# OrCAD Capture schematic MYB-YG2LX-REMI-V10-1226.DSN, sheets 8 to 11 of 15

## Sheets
8 DSI - HDMI & LVDS: size A2; note: Dispaly
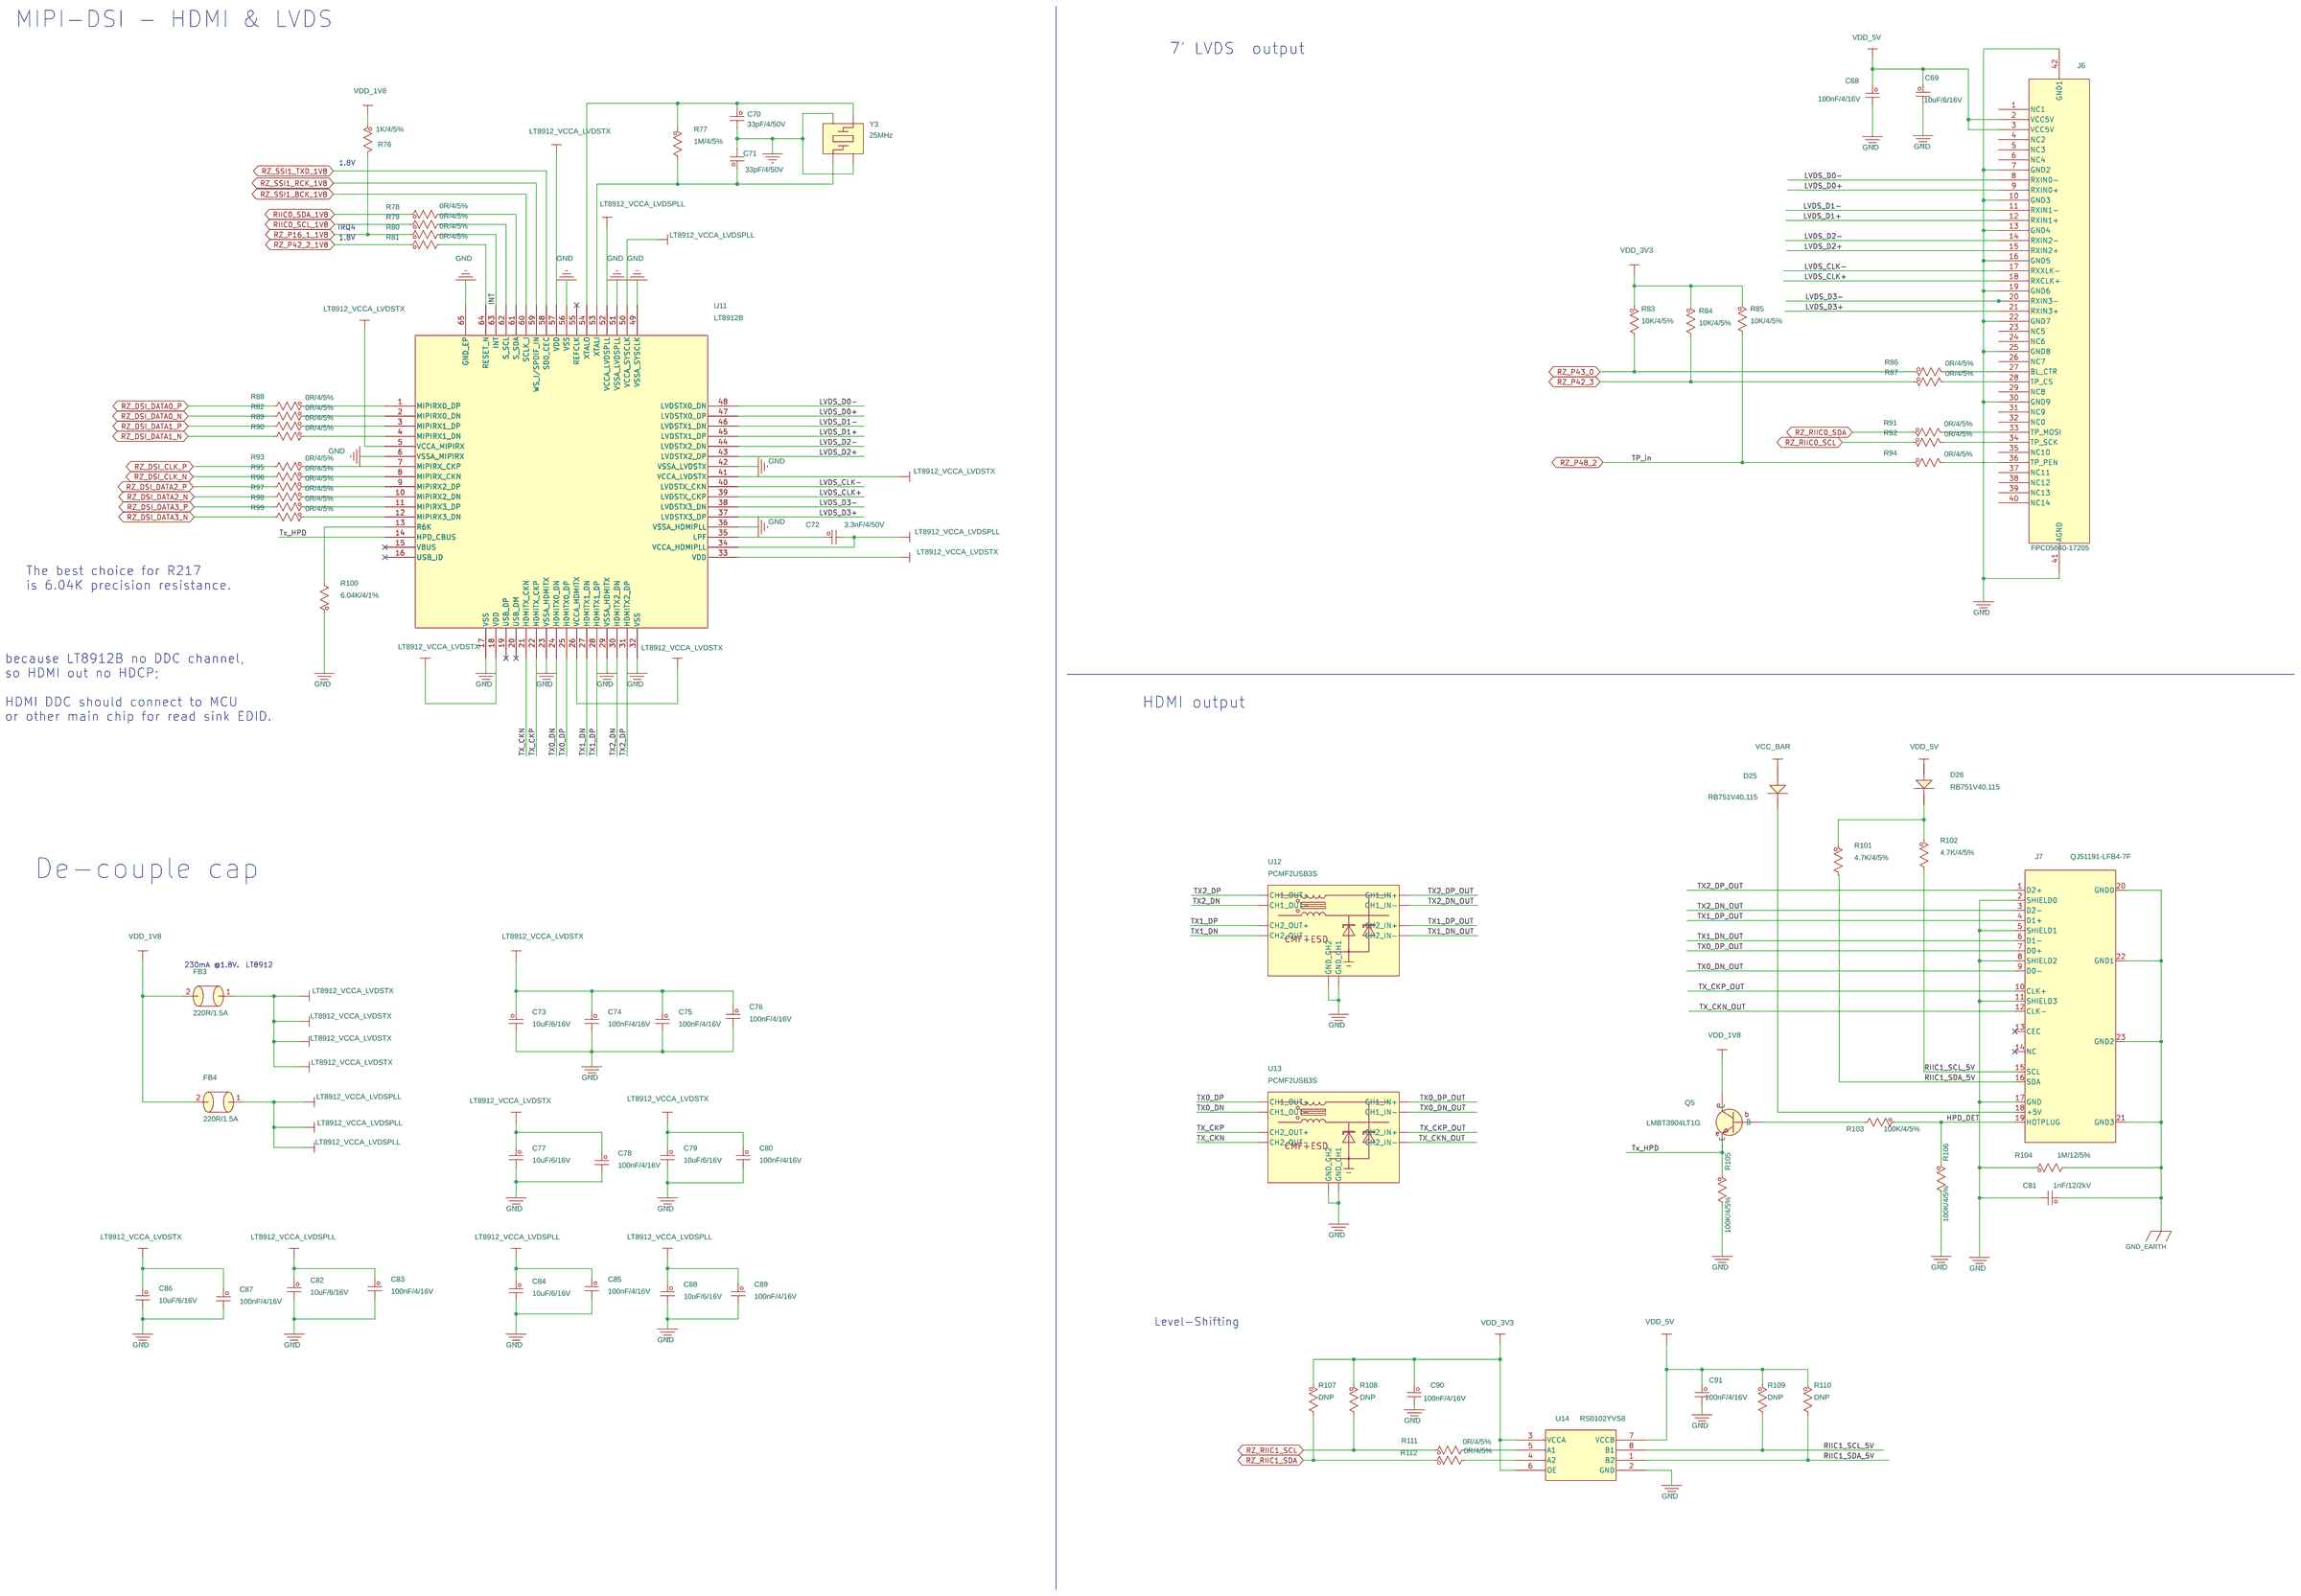
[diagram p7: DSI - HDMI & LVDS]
9 Audio: size A3; note: Audio
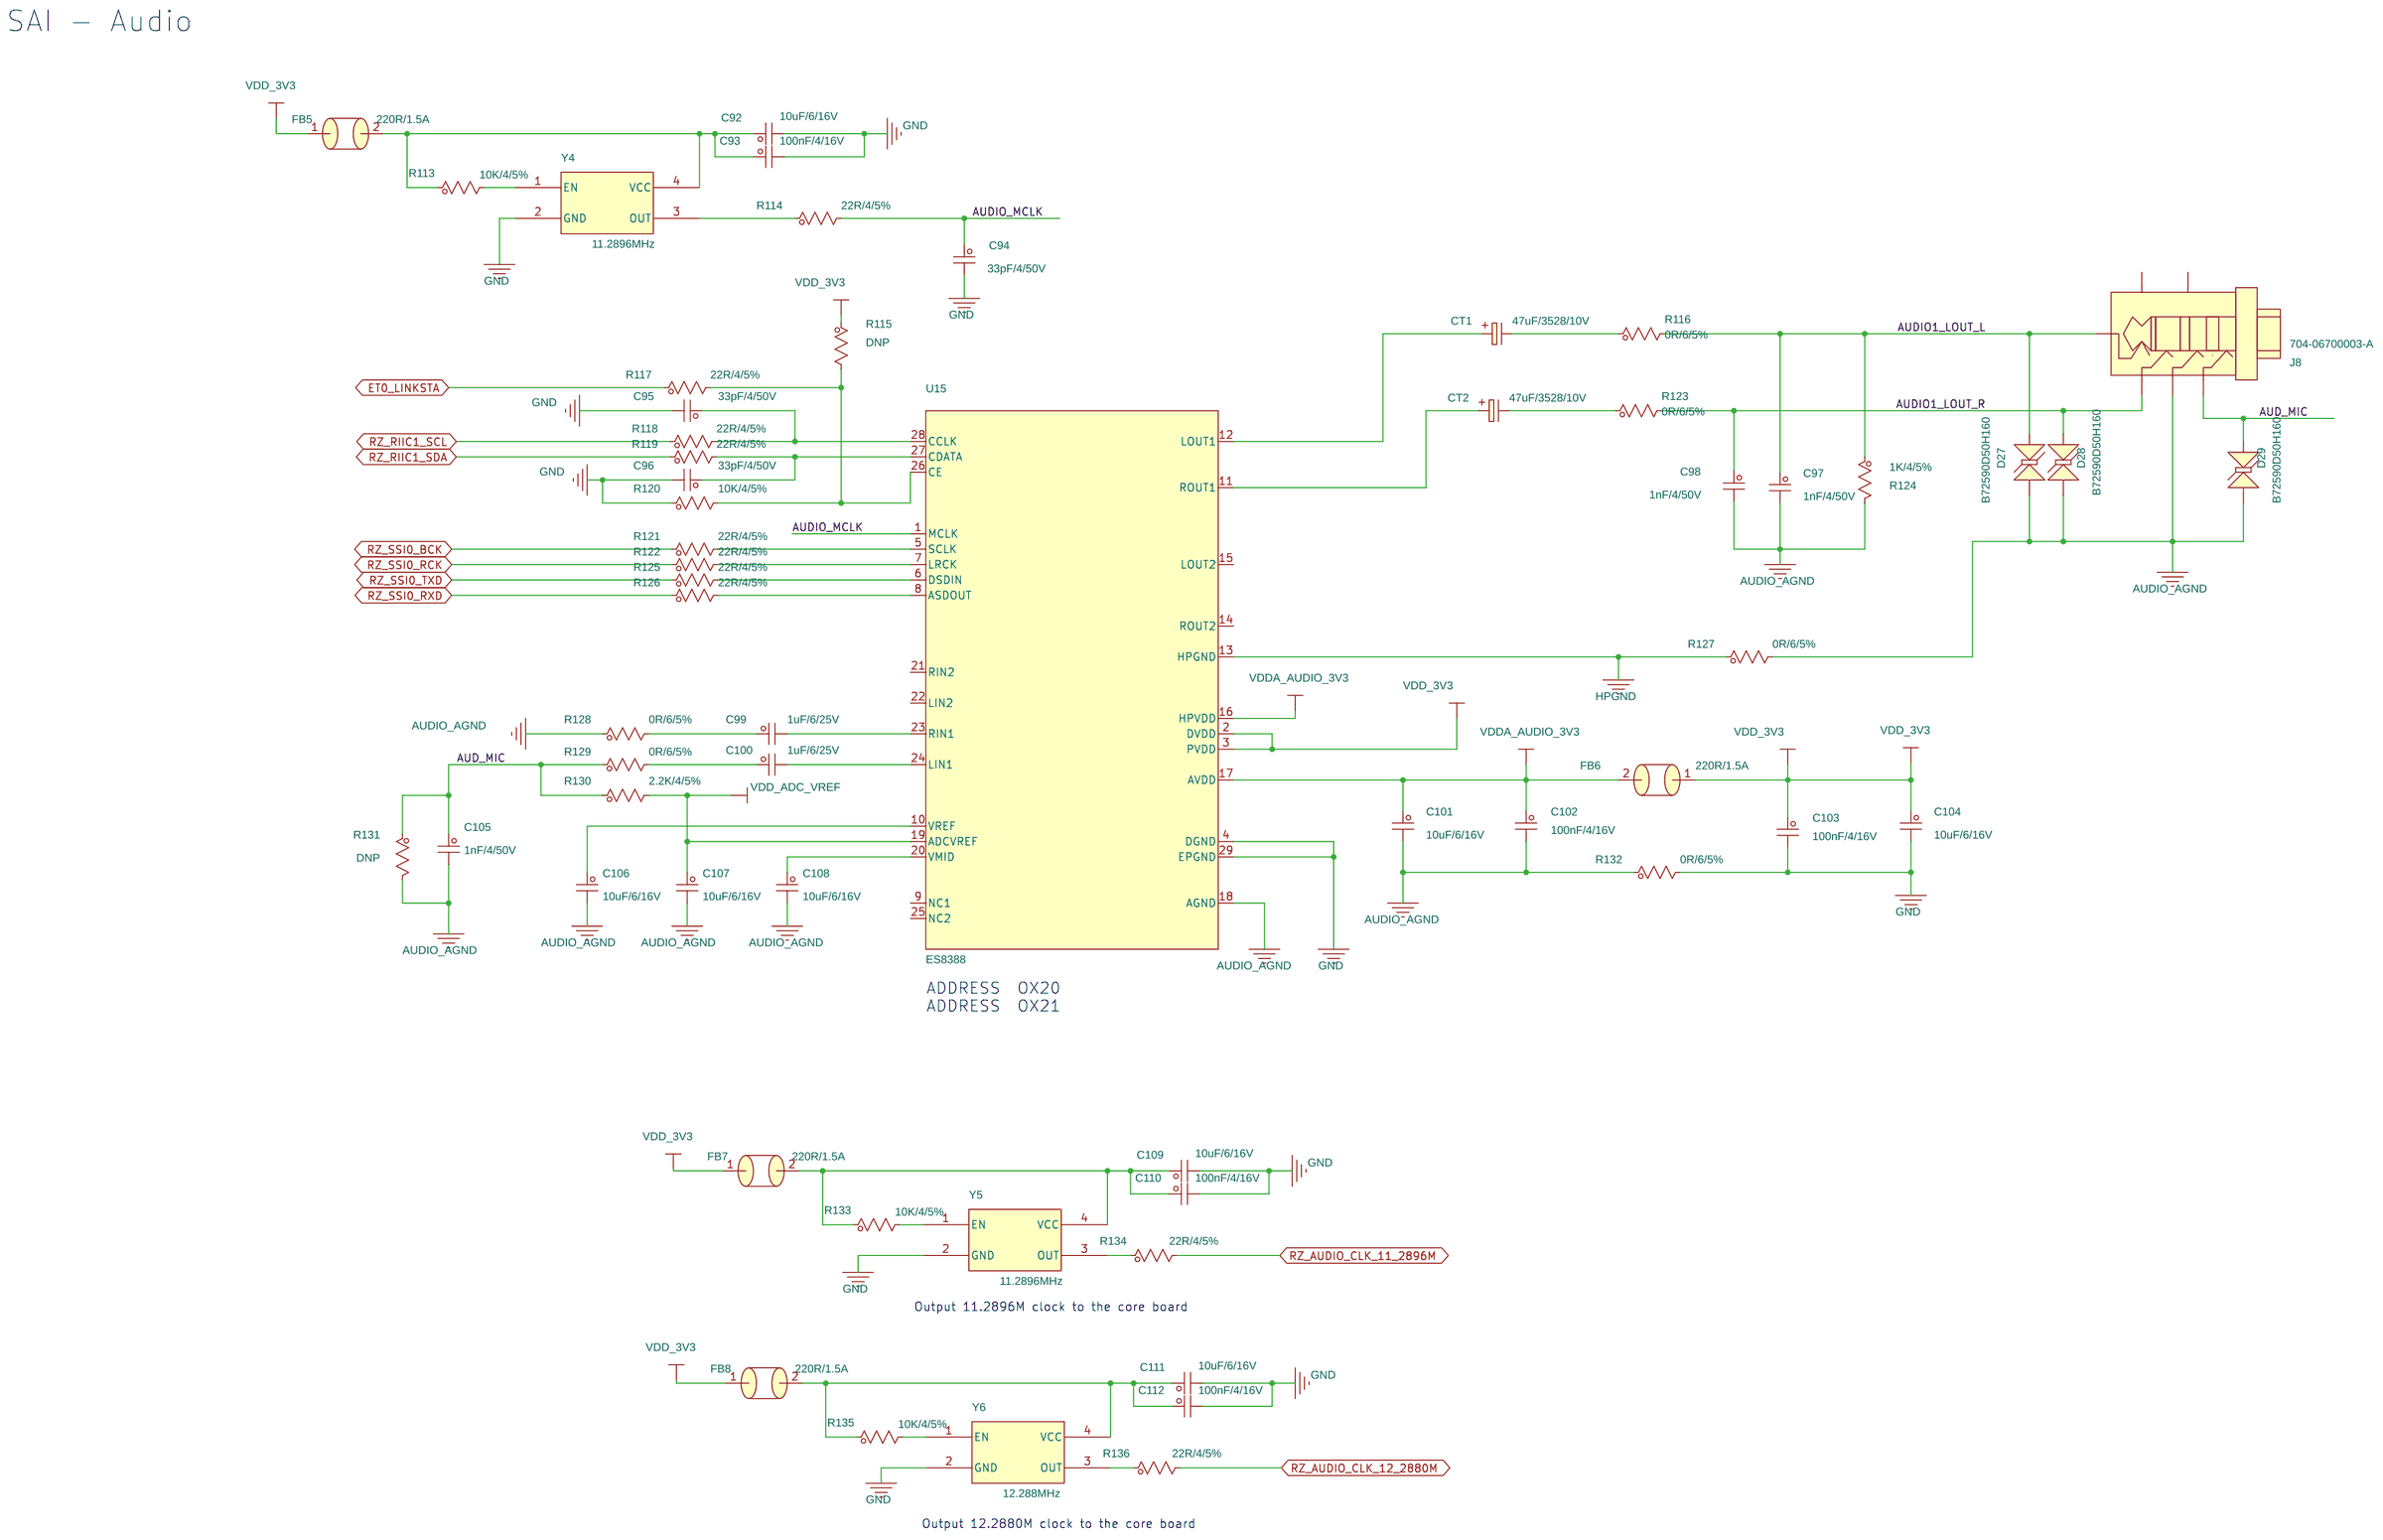
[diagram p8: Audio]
10 ENET0 & ENET1: size A2; note: ENET
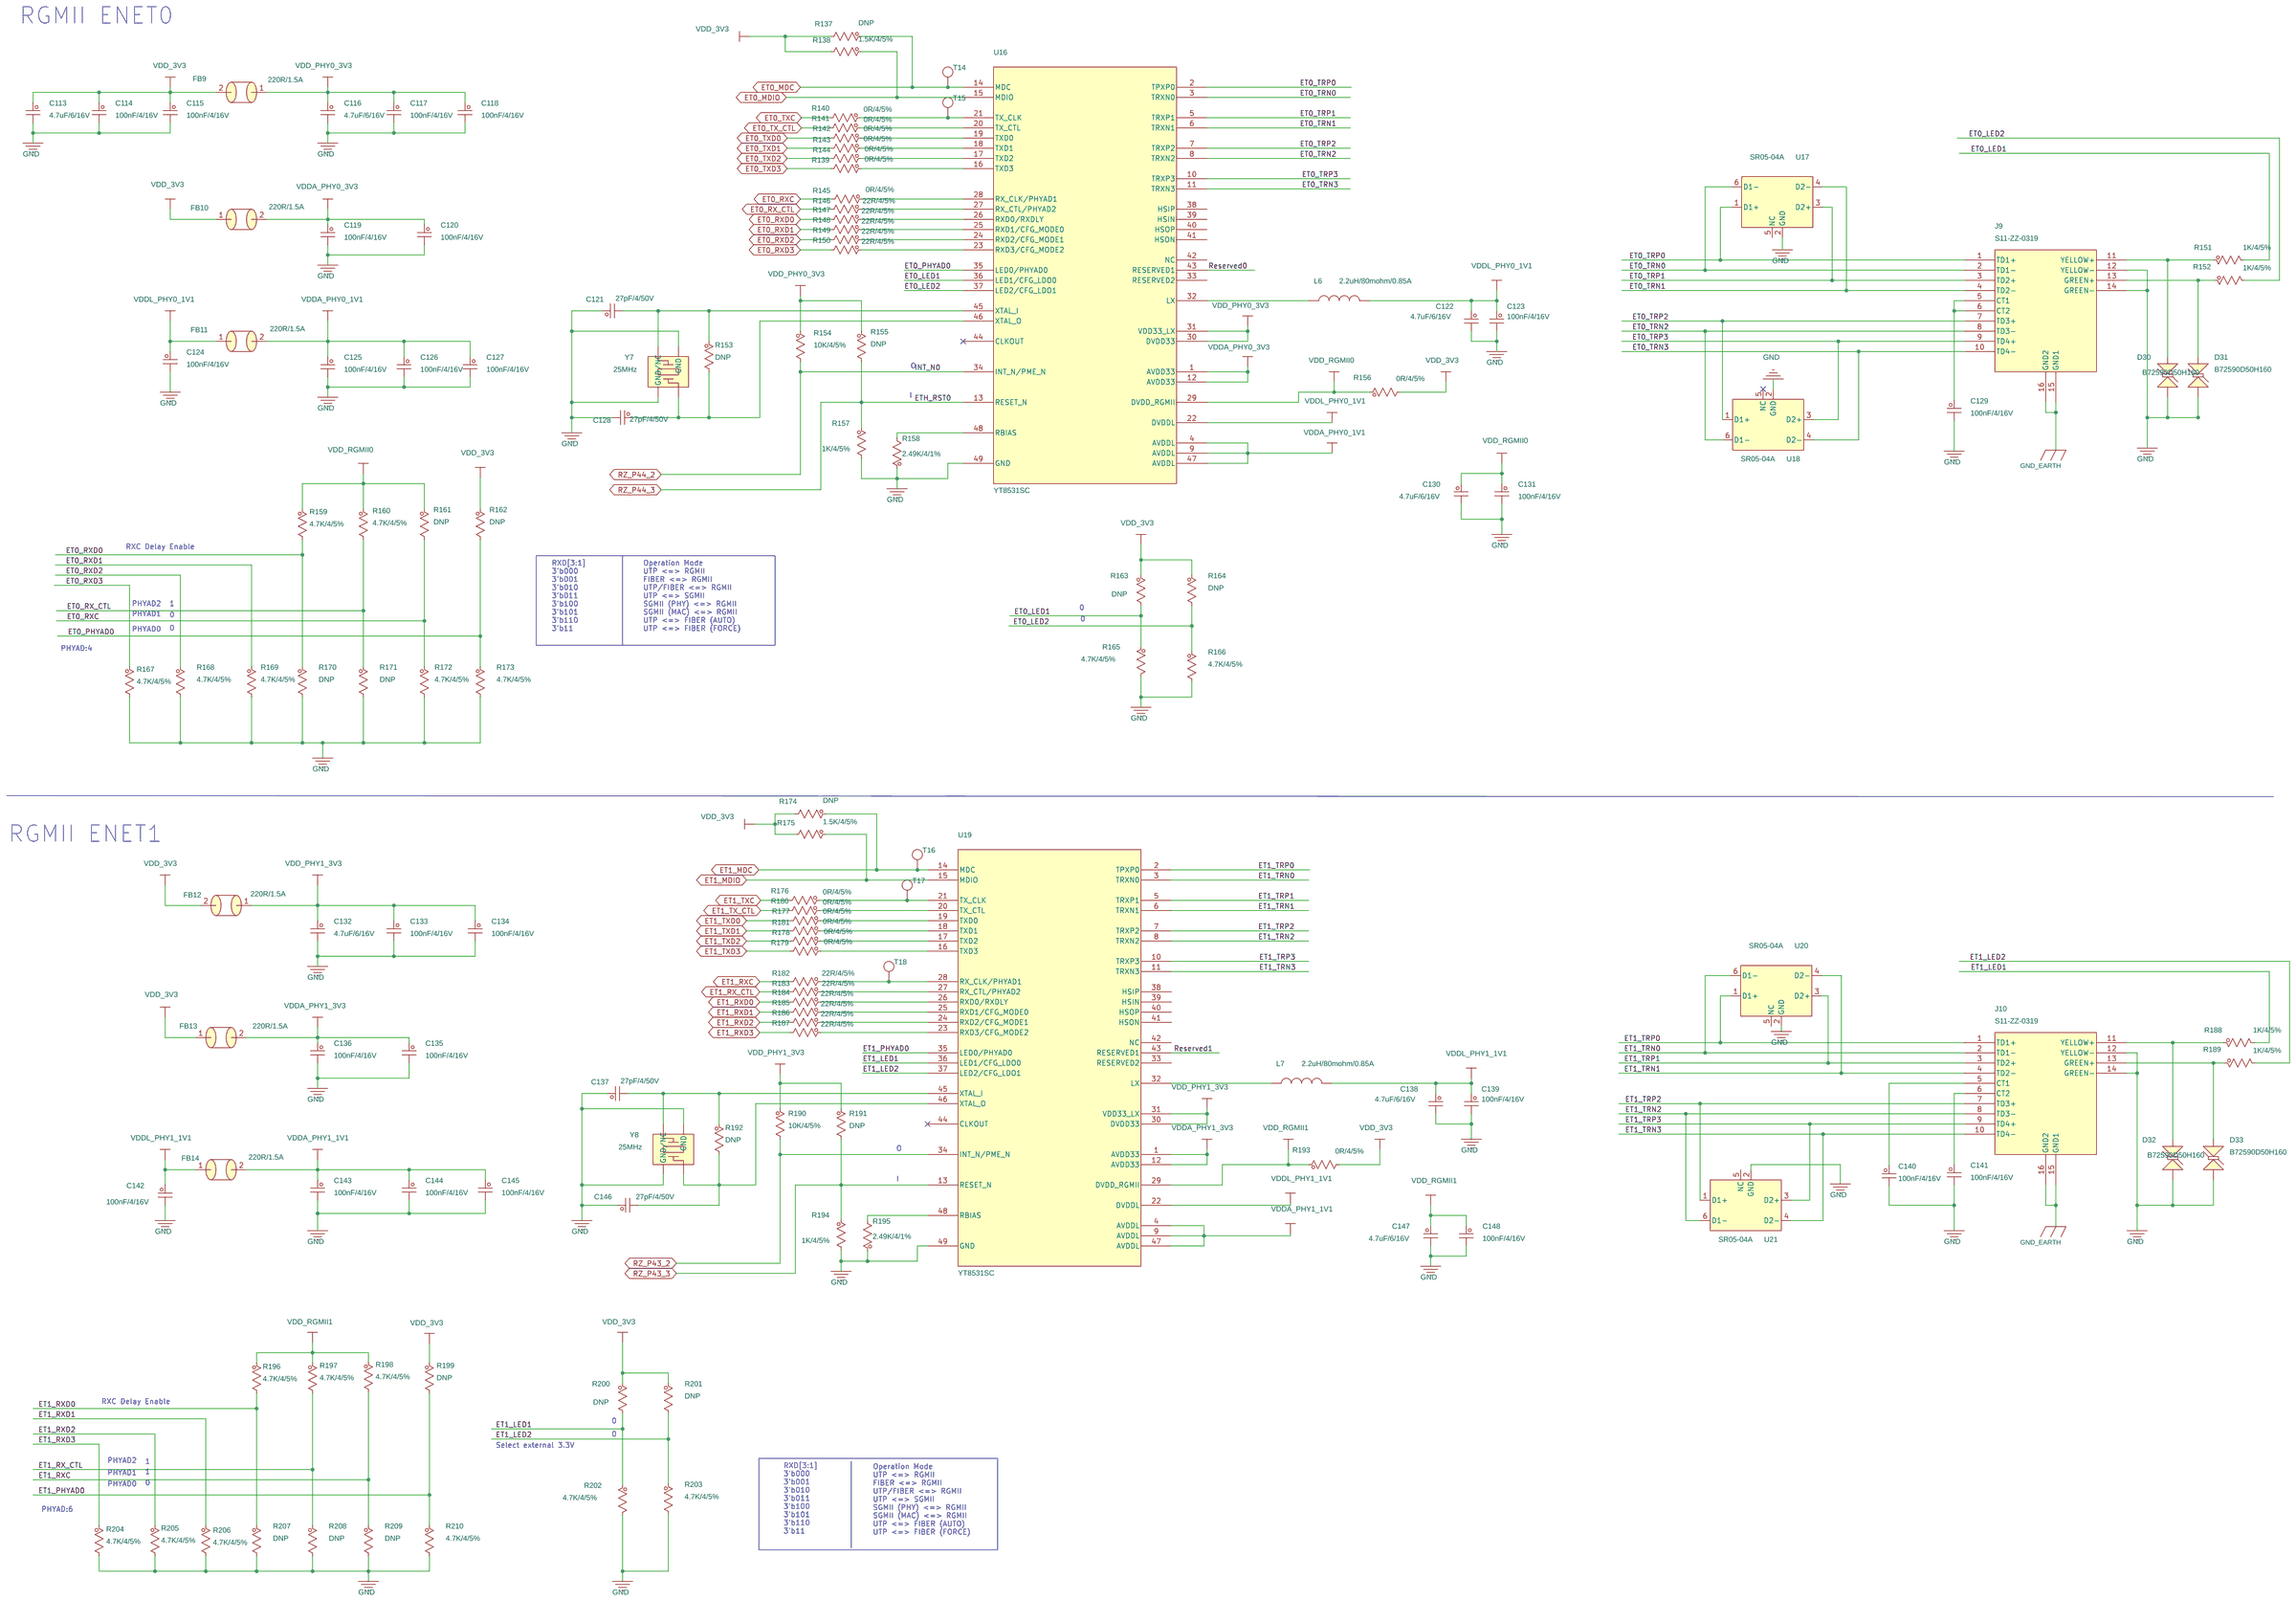
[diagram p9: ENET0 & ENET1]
11 WIFI & BT: size A2; note: MISC
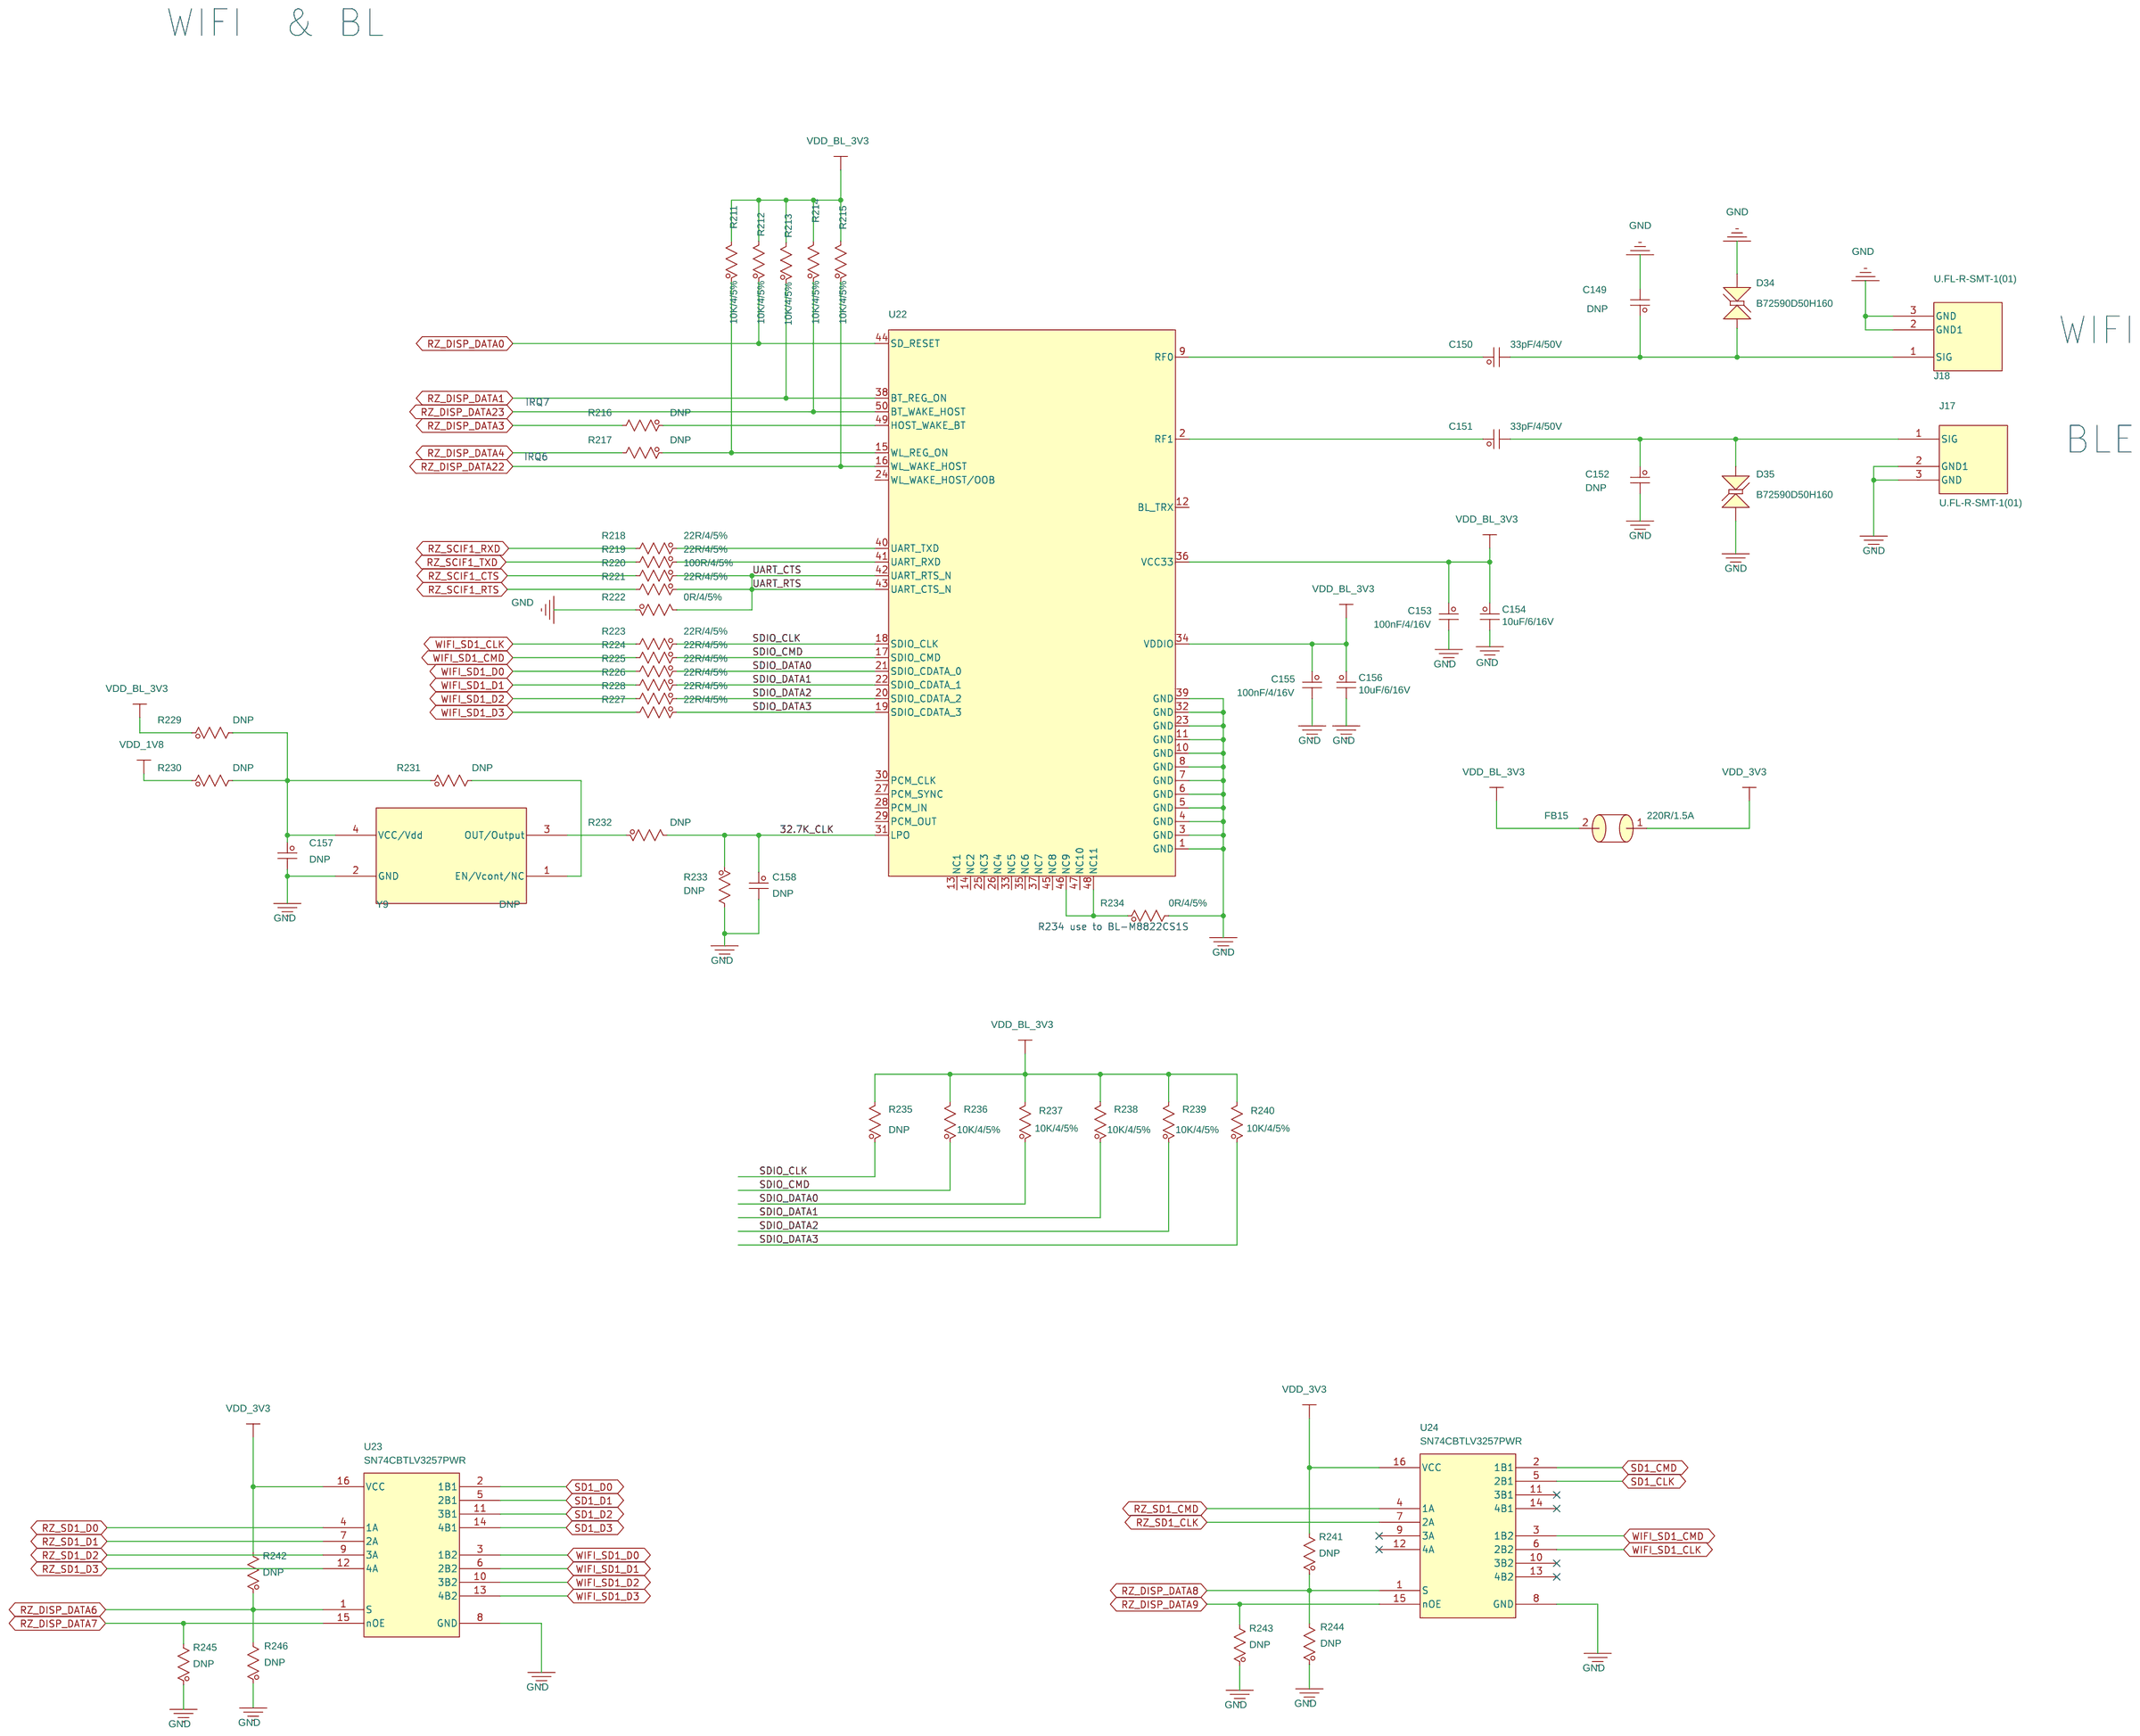
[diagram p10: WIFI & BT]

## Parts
sheet Audio
C92  10uF/6/16V  [C0603]
C93  100nF/4/16V  [C0402]
C94  33pF/4/50V  [C0402]
C95  33pF/4/50V  [C0402]
C96  33pF/4/50V  [C0402]
C97  1nF/4/50V  [C0402]
C98  1nF/4/50V  [C0402]
C99  1uF/6/25V  [C0603]
C100  1uF/6/25V  [C0603]
C101  10uF/6/16V  [C0603]
C102  100nF/4/16V  [C0402]
C103  100nF/4/16V  [C0402]
C104  10uF/6/16V  [C0603]
C105  1nF/4/50V  [C0402]
C106  10uF/6/16V  [C0603]
C107  10uF/6/16V  [C0603]
C108  10uF/6/16V  [C0603]
C109  10uF/6/16V  [C0603]
C110  100nF/4/16V  [C0402]
C111  10uF/6/16V  [C0603]
C112  100nF/4/16V  [C0402]
CT1  47uF/3528/10V  [CT3528-B]
CT2  47uF/3528/10V  [CT3528-B]
D27  B72590D50H160  [D0402]
D28  B72590D50H160  [D0402]
D29  B72590D50H160  [D0402]
FB5  220R/1.5A  [FB0603]
FB6  220R/1.5A  [FB0603]
FB7  220R/1.5A  [FB0603]
FB8  220R/1.5A  [FB0603]
J8  704-06700003-A  [CKX-704]
R113  10K/4/5%  [R0402]
R114  22R/4/5%  [R0402]
R115  DNP  [R0402]
R116  0R/6/5%  [R0603]
R117  22R/4/5%  [R0402]
R118  22R/4/5%  [R0402]
R119  22R/4/5%  [R0402]
R120  10K/4/5%  [R0402]
R121  22R/4/5%  [R0402]
R122  22R/4/5%  [R0402]
R123  0R/6/5%  [R0603]
R124  1K/4/5%  [R0402]
R125  22R/4/5%  [R0402]
R126  22R/4/5%  [R0402]
R127  0R/6/5%  [R0603]
R128  0R/6/5%  [R0603]
R129  0R/6/5%  [R0603]
R130  2.2K/4/5%  [R0402]
R131  DNP  [R0402]
R132  0R/6/5%  [R0603]
R133  10K/4/5%  [R0402]
R134  22R/4/5%  [R0402]
R135  10K/4/5%  [R0402]
R136  22R/4/5%  [R0402]
U15  ES8388  [QFN28-0_45]
Y4  11.2896MHz  [3225]
Y5  11.2896MHz  [3225]
Y6  12.288MHz  [3225]
sheet DSI - HDMI & LVDS
C68  100nF/4/16V  [C0402]
C69  10uF/6/16V  [C0603]
C70  33pF/4/50V  [C0402]
C71  33pF/4/50V  [C0402]
C72  3.3nF/4/50V  [C0402]
C73  10uF/6/16V  [C0603]
C74  100nF/4/16V  [C0402]
C75  100nF/4/16V  [C0402]
C76  100nF/4/16V  [C0402]
C77  10uF/6/16V  [C0603]
C78  100nF/4/16V  [C0402]
C79  10uF/6/16V  [C0603]
C80  100nF/4/16V  [C0402]
C81  1nF/12/2kV  [C1206]
C82  10uF/6/16V  [C0603]
C83  100nF/4/16V  [C0402]
C84  10uF/6/16V  [C0603]
C85  100nF/4/16V  [C0402]
C86  10uF/6/16V  [C0603]
C87  100nF/4/16V  [C0402]
C88  10uF/6/16V  [C0603]
C89  100nF/4/16V  [C0402]
C90  100nF/4/16V  [C0402]
C91  100nF/4/16V  [C0402]
D25  RB751V40,115  [SOD323]
D26  RB751V40,115  [SOD323]
FB3  220R/1.5A  [FB0603]
FB4  220R/1.5A  [FB0603]
J6  FPC05040-17205  [FPC40-0_5-h]
J7  QJ51191-LFB4-7F  [QJ51191-LFB4]
Q5  LMBT3904LT1G  [SOT-23]
R76  1K/4/5%  [R0402]
R77  1M/4/5%  [R0402]
R78  0R/4/5%  [R0402]
R79  0R/4/5%  [R0402]
R80  0R/4/5%  [R0402]
R81  0R/4/5%  [R0402]
R82  0R/4/5%  [R0402]
R83  10K/4/5%  [R0402]
R84  10K/4/5%  [R0402]
R85  10K/4/5%  [R0402]
R86  0R/4/5%  [R0402]
R87  0R/4/5%  [R0402]
R88  0R/4/5%  [R0402]
R89  0R/4/5%  [R0402]
R90  0R/4/5%  [R0402]
R91  0R/4/5%  [R0402]
R92  0R/4/5%  [R0402]
R93  0R/4/5%  [R0402]
R94  0R/4/5%  [R0402]
R95  0R/4/5%  [R0402]
R96  0R/4/5%  [R0402]
R97  0R/4/5%  [R0402]
R98  0R/4/5%  [R0402]
R99  0R/4/5%  [R0402]
R100  6.04K/4/1%  [R0402]
R101  4.7K/4/5%  [R0402]
R102  4.7K/4/5%  [R0402]
R103  100K/4/5%  [R0402]
R104  1M/12/5%  [R1206]
R105  100K/4/5%  [R0402]
R106  100K/4/5%  [R0402]
R107  DNP  [R0402]
R108  DNP  [R0402]
R109  DNP  [R0402]
R110  DNP  [R0402]
R111  0R/4/5%  [R0402]
R112  0R/4/5%  [R0402]
U11  LT8912B  [qfn64-0_4-LT8912B]
U12  PCMF2USB3S  [WLCSP10]
U13  PCMF2USB3S  [WLCSP10]
U14  RS0102YVS8  [VSSOP8]
Y3  25MHz  [3225]
sheet ENET0 & ENET1
C113  4.7uF/6/16V  [C0603]
C114  100nF/4/16V  [C0402]
C115  100nF/4/16V  [C0402]
C116  4.7uF/6/16V  [C0603]
C117  100nF/4/16V  [C0402]
C118  100nF/4/16V  [C0402]
C119  100nF/4/16V  [C0402]
C120  100nF/4/16V  [C0402]
C121  27pF/4/50V  [C0402]
C122  4.7uF/6/16V  [C0603]
C123  100nF/4/16V  [C0402]
C124  100nF/4/16V  [C0402]
C125  100nF/4/16V  [C0402]
C126  100nF/4/16V  [C0402]
C127  100nF/4/16V  [C0402]
C128  27pF/4/50V  [C0402]
C129  100nF/4/16V  [C0402]
C130  4.7uF/6/16V  [C0603]
C131  100nF/4/16V  [C0402]
C132  4.7uF/6/16V  [C0603]
C133  100nF/4/16V  [C0402]
C134  100nF/4/16V  [C0402]
C135  100nF/4/16V  [C0402]
C136  100nF/4/16V  [C0402]
C137  27pF/4/50V  [C0402]
C138  4.7uF/6/16V  [C0603]
C139  100nF/4/16V  [C0402]
C140  100nF/4/16V  [C0402]
C141  100nF/4/16V  [C0402]
C142  100nF/4/16V  [C0402]
C143  100nF/4/16V  [C0402]
C144  100nF/4/16V  [C0402]
C145  100nF/4/16V  [C0402]
C146  27pF/4/50V  [C0402]
C147  4.7uF/6/16V  [C0603]
C148  100nF/4/16V  [C0402]
D30  B72590D50H160  [D0402]
D31  B72590D50H160  [D0402]
D32  B72590D50H160  [D0402]
D33  B72590D50H160  [D0402]
FB9  220R/1.5A  [FB0603]
FB10  220R/1.5A  [FB0603]
FB11  220R/1.5A  [FB0603]
FB12  220R/1.5A  [FB0603]
FB13  220R/1.5A  [FB0603]
FB14  220R/1.5A  [FB0603]
J9  S11-ZZ-0319  [S11-ZZ-0319]
J10  S11-ZZ-0319  [S11-ZZ-0319]
L6  2.2uH/80mohm/0.85A  [L2x2_5]
L7  2.2uH/80mohm/0.85A  [L2x2_5]
R137  DNP  [R0402]
R138  1.5K/4/5%  [R0402]
R139  0R/4/5%  [R0402]
R140  0R/4/5%  [R0402]
R141  0R/4/5%  [R0402]
R142  0R/4/5%  [R0402]
R143  0R/4/5%  [R0402]
R144  0R/4/5%  [R0402]
R145  0R/4/5%  [R0402]
R146  22R/4/5%  [R0402]
R147  22R/4/5%  [R0402]
R148  22R/4/5%  [R0402]
R149  22R/4/5%  [R0402]
R150  22R/4/5%  [R0402]
R151  1K/4/5%  [R0402]
R152  1K/4/5%  [R0402]
R153  DNP  [R0402]
R154  10K/4/5%  [R0402]
R155  DNP  [R0402]
R156  0R/4/5%  [R0402]
R157  1K/4/5%  [R0402]
R158  2.49K/4/1%  [R0402]
R159  4.7K/4/5%  [R0402]
R160  4.7K/4/5%  [R0402]
R161  DNP  [R0402]
R162  DNP  [R0402]
R163  DNP  [R0402]
R164  DNP  [R0402]
R165  4.7K/4/5%  [R0402]
R166  4.7K/4/5%  [R0402]
R167  4.7K/4/5%  [R0402]
R168  4.7K/4/5%  [R0402]
R169  4.7K/4/5%  [R0402]
R170  DNP  [R0402]
R171  DNP  [R0402]
R172  4.7K/4/5%  [R0402]
R173  4.7K/4/5%  [R0402]
R174  DNP  [R0402]
R175  1.5K/4/5%  [R0402]
R176  0R/4/5%  [R0402]
R177  0R/4/5%  [R0402]
R178  0R/4/5%  [R0402]
R179  0R/4/5%  [R0402]
R180  0R/4/5%  [R0402]
R181  0R/4/5%  [R0402]
R182  22R/4/5%  [R0402]
R183  22R/4/5%  [R0402]
R184  22R/4/5%  [R0402]
R185  22R/4/5%  [R0402]
R186  22R/4/5%  [R0402]
R187  22R/4/5%  [R0402]
R188  1K/4/5%  [R0402]
R189  1K/4/5%  [R0402]
R190  10K/4/5%  [R0402]
R191  DNP  [R0402]
R192  DNP  [R0402]
R193  0R/4/5%  [R0402]
R194  1K/4/5%  [R0402]
R195  2.49K/4/1%  [R0402]
R196  4.7K/4/5%  [R0402]
R197  4.7K/4/5%  [R0402]
R198  4.7K/4/5%  [R0402]
R199  DNP  [R0402]
R200  DNP  [R0402]
R201  DNP  [R0402]
R202  4.7K/4/5%  [R0402]
R203  4.7K/4/5%  [R0402]
R204  4.7K/4/5%  [R0402]
R205  4.7K/4/5%  [R0402]
R206  4.7K/4/5%  [R0402]
R207  DNP  [R0402]
R208  DNP  [R0402]
R209  DNP  [R0402]
R210  4.7K/4/5%  [R0402]
T14  SMD  [test0_8-smd]
T15  SMD  [test0_8-smd]
T16  SMD  [test0_8-smd]
T17  SMD  [test0_8-smd]
T18  SMD  [test0_8-smd]
U16  YT8531SC  [QFN48-0_4]
U17  SR05-04A  [SOT23-6]
U18  SR05-04A  [SOT23-6]
U19  YT8531SC  [QFN48-0_4]
U20  SR05-04A  [SOT23-6]
U21  SR05-04A  [SOT23-6]
Y7  25MHz  [3225]
Y8  25MHz  [3225]
sheet WIFI & BT
C149  DNP  [C0402]
C150  33pF/4/50V  [C0402]
C151  33pF/4/50V  [C0402]
C152  DNP  [C0402]
C153  100nF/4/16V  [C0402]
C154  10uF/6/16V  [C0603]
C155  100nF/4/16V  [C0402]
C156  10uF/6/16V  [C0603]
C157  DNP  [C0402]
C158  DNP  [C0402]
D34  B72590D50H160  [D0402]
D35  B72590D50H160  [D0402]
FB15  220R/1.5A  [FB0603]
J17  U.FL-R-SMT-1(01)  [FL_2d95x1d55_2sp]
J18  U.FL-R-SMT-1(01)  [FL_2d95x1d55_2sp]
R211  10K/4/5%  [R0402]
R212  10K/4/5%  [R0402]
R213  10K/4/5%  [R0402]
R214  10K/4/5%  [R0402]
R215  10K/4/5%  [R0402]
R216  DNP  [R0402]
R217  DNP  [R0402]
R218  22R/4/5%  [R0402]
R219  22R/4/5%  [R0402]
R220  100R/4/5%  [R0402]
R221  22R/4/5%  [R0402]
R222  0R/4/5%  [R0402]
R223  22R/4/5%  [R0402]
R224  22R/4/5%  [R0402]
R225  22R/4/5%  [R0402]
R226  22R/4/5%  [R0402]
R227  22R/4/5%  [R0402]
R228  22R/4/5%  [R0402]
R229  DNP  [R0402]
R230  DNP  [R0402]
R231  DNP  [R0402]
R232  DNP  [R0402]
R233  DNP  [R0402]
R234  0R/4/5%  [R0402]
R235  DNP  [R0402]
R236  10K/4/5%  [R0402]
R237  10K/4/5%  [R0402]
R238  10K/4/5%  [R0402]
R239  10K/4/5%  [R0402]
R240  10K/4/5%  [R0402]
R241  DNP  [R0402]
R242  DNP  [R0402]
R243  DNP  [R0402]
R244  DNP  [R0402]
R245  DNP  [R0402]
R246  DNP  [R0402]
U22  BL-M8822CS1S  [MODULE-L297B-SR]
U23  SN74CBTLV3257PWR  [TSSOP16]
U24  SN74CBTLV3257PWR  [TSSOP16]
Y9  DNP  [3225]

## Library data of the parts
C92 C109 C111 = CERAMIC_CAPACITOR: Ceramic Capacitor,10uF,16V,+/-20%,X5R,0603,Samsung; Manufacturer: Samsung; Manufacturer P/N: CL10A106MONQNC; Myir P/N: 20401.80062; Part Type: Ceramic Capacitor; Reserve Value: 10uF; Datasheet: Samsung.pdf
C68 C74-C76 C78 C80 C83 C85 C87 C89-C91 C93 C102 C103 C110 C112 C114 C115 C117-C120 C123-C127 C129 C131 C133-C136 C139-C145 C148 C153 C155 C157 C158 = Ceramic_Capacitor: Ceramic Capacitor,100nF,16V,+/-10%,X7R,0402,Fenghua; Manufacturer: Fenghua; Manufacturer P/N: 0402B104K160NT; Myir P/N: 20401.80188; Part Type: Ceramic Capacitor; Reserve Value: 100nF; Datasheet: FENGHUA-Capacitor.pdf
C70 C71 C94-C96 C150 C151 = Ceramic_Capacitor: Ceramic Capacitor,33pF,50V,+/-5%,C0G,0402,Fenghua; Manufacturer: Fenghua; Manufacturer P/N: 0402CG330J500NT; Myir P/N: 20401.00091; Part Type: Ceramic Capacitor; Reserve Value: 33pF; Datasheet: FENGHUA-Capacitor.pdf
C97 C98 C105 = Ceramic_Capacitor: Ceramic Capacitor,1nF,50V,+/-10%,X7R,0402,Fenghua; Manufacturer: Fenghua; Manufacturer P/N: 0402B102K500NT; Myir P/N: 20401.80096; Part Type: Ceramic Capacitor; Reserve Value: 1nF; Datasheet: FENGHUA-Capacitor.pdf
C99 C100 = Ceramic_Capacitor: Ceramic Capacitor,1uF,+/-10%,X5R,SMT,25V,0603,Samsung; Manufacturer: Samsung; Manufacturer P/N: CL10A105KA8NNNC; Myir P/N: 20401.80063; Part Type: Ceramic Capacitor; Reserve Value: 1uF; Datasheet: Samsung.pdf
C101 C104 C106-C108 C154 C156 = Ceramic_Capacitor: Ceramic Capacitor,10uF,+/-20%,X5R,16V,SMD,0603,Samsung; Manufacturer: Samsung; Manufacturer P/N: CL10A106MO8NQNC; Myir P/N: 20401.80062; Part Type: Ceramic Capacitor; Reserve Value: 10uF; Datasheet: Samsung.pdf
CT1 CT2 = Tantalum_Capacitor: Tantalum Capacitor,47uF,+/-10%,10V,SMD,3528(B),AVX; Manufacturer: AVX; Manufacturer P/N: TAJB476K010RNJ; Myir P/N: 20403.00006; Part Type: Tantalum Capacitor; Reserve Value: 47uF; Datasheet: Tantalum Capacitor.pdf
D27-D35 = TVS_Diode: Diode,TVS,5.6VDC,SMD,D0402,TDK; Manufacturer: TDK; Myir P/N: 20701.00001; Part Type: Diode; Datasheet: B72590D0050H160.pdf
FB3-FB15 = Ferrite_Bead: Ferrite Bead,220R@100Mhz,1.5A,+/-25%,SMD,0603,Fenghua; Manufacturer: Fenghua; Manufacturer P/N: CBM160808U221T; Myir P/N: 20601.80007; Part Type: Ferrite Bead; Reserve Value: 220R; Datasheet: CBM160808U221T.pdf
J8 = Audio-704-06700003-A: Connector,Φ3.50mm with 4 Pole with single audio jack,SMD,Reel,SongCheng; Manufacturer: SongCheng; Myir P/N: 21116.00006; Part Type: Audio Connector; Datasheet: 704-06700003-A.pdf
R83-R85 R113 R133 R135 R163 R164 R200 R201 = Resister: Thick Film Resistor,10K,+/-5%,1/16W,-55°C ~ 155°C,SMD,0402,Fenghua; Manufacturer: Fenghua; Manufacturer P/N: RC-02W103JT; Myir P/N: 20301.00199; Part Type: Thick Film Resistor; Reserve Value: 10K; Datasheet: FH规格书_2018-07-30.pdf
R114 R216-R219 R221 R223-R228 = Resister: Thick Film Resistor,22R,+/-5%,1/16W,-55℃~155℃,SMD,0402,Fenghua; Manufacturer: Fenghua; Manufacturer P/N: RC-02W220JT; Myir P/N: 20301.00187; Part Type: Thick Film Resistor; Reserve Value: 22R; Datasheet: FHsheet_2018-07-30.PDF
R115 R154 R155 R190 R191 = Resister: Thick Film Resistor,10K,+/-5%,1/16W,-55°C ~ 155°C,SMD,0402,Fenghua; Manufacturer: Fenghua; Manufacturer P/N: RC-02W103JT; Myir P/N: 20301.00199; Part Type: Thick Film Resistor; Reserve Value: 10K; Datasheet: FHsheet_2018-07-30.PDF
R116 R123 R127 R132 = Resister: Thick Film Resistor,0R,+/-5%,1/10W,-55°C ~ 155°C,SMD,0603,Fenghua; Manufacturer: Fenghua; Manufacturer P/N: RS-03000JT; Myir P/N: 20301.00214; Part Type: Thick Film Resistor; Reserve Value: 0R; Datasheet: FHsheet_2018-07-30.PDF
R117-R119 R121 R122 R125 R126 = Resister: Thick Film Resistor,22R,+/-5%,1/16W,-55℃~155℃,SMD,0402,Fenghua; Manufacturer: Fenghua; Manufacturer P/N: RC-02K220JT; Myir P/N: 20301.00187; Part Type: Thick Film Resistor; Reserve Value: 22R; Datasheet: FHsheet-20230524.pdf
R120 = Resister: Thick Film Resistor,10K,+/-5%,1/16W,-55℃~155℃,SMD,0402,Fenghua; Manufacturer: Fenghua; Manufacturer P/N: RC-02K103JT; Myir P/N: 20301.00199; Part Type: Thick Film Resistor; Reserve Value: 10K; Datasheet: FHsheet-20230524.pdf
R124 = Resister: Thick Film Resistor,1K,+/-5%,1/16W,-55℃~155℃,SMD,0402,Fenghua; Manufacturer: Fenghua; Manufacturer P/N: RC-02K102JT; Myir P/N: 20301.80389; Part Type: Thick Film Resistor; Reserve Value: 1K; Datasheet: FHsheet-20230524.pdf
R128 R129 = Resister: Thick Film Resistor,0R,+/-5%,1/10W,-55℃~155℃,SMD,0603,Fenghua; Manufacturer: Fenghua; Manufacturer P/N: RS-03000JT; Myir P/N: 20301.00214; Part Type: Thick Film Resistor; Reserve Value: 0R; Datasheet: FHsheet-20230524.pdf
R130 = Resister: Thick Film Resistor,2.2K,+/-5%,1/16W,-55℃~155℃,SMD,0402,Fenghua; Manufacturer: Fenghua; Manufacturer P/N: RC-02K222JT; Myir P/N: 20301.00195; Part Type: Thick Film Resistor; Reserve Value: 2.2K; Datasheet: FHsheet-20230524.pdf
R131 = Resister: Thick Film Resistor,2.2K,+/-5%,1/16W,-55℃~155℃,SMD,0402,Fenghua; Manufacturer: Fenghua; Manufacturer P/N: RC-02W222JT; Myir P/N: 20301.00195; Part Type: Thick Film Resistor; Reserve Value: 2.2K; Datasheet: FHsheet_2018-07-30.PDF
R134 R136 = Resister: Thick Film Resistor,22R,+/-5%,1/16W,-55°C ~ 155°C,SMD,0402,Fenghua; Manufacturer: Fenghua; Manufacturer P/N: RC-02W220JT; Myir P/N: 20301.00187; Part Type: Thick Film Resistor; Reserve Value: 22R; SIGNAL_MODEL: RESISTER_R0402_22/4/5%_22/4/5%; Datasheet: FH规格书_2018-07-30.pdf
U15 = ES8388: IC,Low Power Stereo Audio CODEC With Headphone Amplifier,-40~85℃,SMD,QFN28,Tray,Everest; Manufacturer: Everest; Myir P/N: 20107.00093; Part Type: Interface; Datasheet: ES8388DS.pdf
Y4 Y5 = Oscillator_4P_v3: Oscillator,11.2896MHz,+/-20ppm,15pF,3.3V,4Pin,3225,-40℃ to +85℃,SMD,SJK; Manufacturer: SJK; Manufacturer P/N: SJK-3N11289M3C0420B8; Myir P/N: 20902.00016; Part Type: Oscillator; Datasheet: SJK-3N11289M3C0420B8.pdf
Y6 = Oscillator_4P_v3: Oscillator,12.2880MHz,+/-20ppm,15pF,3.3V,4Pin,3225,-40℃ to +85℃,SMD,SJK; Manufacturer: SJK; Manufacturer P/N: SJK-3N12288M3C0420B8; Myir P/N: 20902.00015; Part Type: Oscillator; Datasheet: SJK-3N12288M3C0420B8.pdf
C69 C73 C77 C79 C82 C84 C86 C88 = Ceramic_Capacitor: Ceramic Capacitor,10uF,16V,+/-20%,X5R,0603,Samsung; Manufacturer: Samsung; Manufacturer P/N: CL10A106MONQNC; Myir P/N: 20401.80062; Part Type: Ceramic Capacitor; Reserve Value: 10uF; Datasheet: Samsung.pdf
C72 = Ceramic_Capacitor: Ceramic Capacitor,3.3nF, 50V,+/-10%,,X7R,0402,Fenghua; Manufacturer: Fenghua; Manufacturer P/N: 0402B332K500NT; Myir P/N: 20401.80104; Part Type: Ceramic Capacitor; Reserve Value: 3.3nF; Datasheet: FENGHUA-Capacitor.pdf
C81 = Ceramic_Capacitor: Ceramic Capacitor,1nF,+/-10%,2kV,X7R,SMD,1206,Fenghua; Manufacturer: Fenghua; Manufacturer P/N: 1206B102K202NT; Myir P/N: 20401.00078; Part Type: Ceramic Capacitor; Reserve Value: 1nF; Datasheet: FENGHUA-Capacitor.pdf
D25 D26 = General_Diode: Diode Schottky, 40V 0.12A,SMD  2-Pin SOD-323,W8,NXP; Manufacturer: NXP; Myir P/N: 20701.00009; Part Type: Diode; Datasheet: RB751_SER.pdf
J6 = FPC40: FPC Connector,40pin,0.5mm pitch,Dual-sided Contact Models, Operating temperature range from–45~85℃,Atom; Manufacturer: Atom; Myir P/N: 21106.00016; Part Type: FPC Connector; Datasheet: FPC_Atom.pdf
J7 = HDMI: Connector,HDMI A port,x1,Right Angle,Female,Gold Flash 1u,black,SMD,Foxconn; Manufacturer: Foxconn; Myir P/N: 21108.00004; Part Type: Display Connector; Datasheet: QJ51191-LFB4-7F.pdf
Q5 = NPN_Transistor: BJT,NPN,40V,200mA,SMD,SOT-23,LRC; Manufacturer: LRC; Myir P/N: 20702.00005; Part Type: BJT; Datasheet: LMBT3904LT1G.pdf
R76 R233 R241-R246 = Resister: Thick Film Resistor,1K,+/-5%,1/16W,-55°C ~ 155°C,SMD,0402,Fenghua; Manufacturer: Fenghua; Manufacturer P/N: RC-02W102JT; Myir P/N: 20301.80389; Part Type: Thick Film Resistor; Reserve Value: 1K; Datasheet: FHsheet_2018-07-30.PDF
R77 = Resister: Thick Film Resistor,1M,+/-5%,1/16W,-55°C ~ 155°C,SMD,0402,Fenghua; Manufacturer: Fenghua; Manufacturer P/N: RC-02W105JT; Myir P/N: 20301.00248; Part Type: Thick Film Resistor; Reserve Value: 1M; Datasheet: FH规格书_2018-07-30.pdf
R78-R82 R86-R99 R111 R112 R139-R145 R156 R176-R181 R193 = Resister: Thick Film Resistor,0R,+/-5%,1/16W,-55°C ~ 155°C,SMD,0402,Fenghua; Manufacturer: Fenghua; Manufacturer P/N: RC-02000JT; Myir P/N: 20301.00186; Part Type: Thick Film Resistor; Reserve Value: 0R; Datasheet: FH规格书_2018-07-30.pdf
R100 = Resister: Thick Film Resistor,6.04K,+/-1%,1/16W,-55°C ~ 155°C,SMD,0402,Fenghua; Manufacturer: Fenghua; Manufacturer P/N: RC-02W6041FT; Myir P/N: 20301.00270; Part Type: Thick Film Resistor; Reserve Value: 6.04K; Datasheet: FH规格书_2018-07-30.pdf
R101 R102 R159-R162 R165-R173 R196-R199 R202-R210 = Resister: Thick Film Resistor,4.7K,+/-5%,1/16W,-55°C ~ 155°C,SMD,0402,Fenghua; Manufacturer: Fenghua; Manufacturer P/N: RC-02W472JT; Myir P/N: 20301.80393; Part Type: Thick Film Resistor; Reserve Value: 4.7K; Datasheet: FH规格书_2018-07-30.pdf
R103 R105 R106 = Resister: Thick Film Resistor,100K,+/-5%,,1/16W,-55°C ~ 155°C,SMD,0402,Fenghua; Manufacturer: Fenghua; Manufacturer P/N: RC-02W104JT; Myir P/N: 20301.00210; Part Type: Thick Film Resistor; Reserve Value: 100K; Datasheet: FH规格书_2018-07-30.pdf
R104 = Resister: Thick Film Resistor,1M,+/-5%,1/4W,-55°C ~ 155°C,SMD,1206,Fenghua; Manufacturer: Fenghua; Manufacturer P/N: RS-06K105JT; Myir P/N: 20301.00226; Part Type: Thick Film Resistor; Reserve Value: 1M; Datasheet: FH规格书_2018-07-30.pdf
R107-R110 = RESISTER: Thick Film Resistor,2.2K,+/-5%,1/16W,-55°C ~ 155°C,SMD,0402,Fenghua; Manufacturer: Fenghua; Manufacturer P/N: RC-02W222JT; Myir P/N: 20301.00195; Part Type: Thick Film Resistor; Reserve Value: 2.2K; Datasheet: FH规格书_2018-07-30.pdf
U11 = LT8912B: IC,LT8912 Single-Channel MIPI? DSI Bridge to LVDS/HDMI,Single 1.8V supply power, ?40°C to +85°C,QFN64(7.5*7.5),Lontium Semiconductor.; Manufacturer: Lontium Semiconductor; Myir P/N: 20107.00050; Part Type: Interface; Datasheet: LT8912_Datasheet_R1.11.pdf
U12 U13 = PCMF2USB3S: IC,Common-mode EMI filter for 2 channels with integrated ESD protection,SMD,WLCSP10,PF2S,NXP; Manufacturer: NXP; Myir P/N: 20114.00011; Part Type: Protection; Datasheet: PCMFxUSB3S.pdf
U14 = TXS0102DCT: IC,2-Bit Bidirectional Voltage-Level Translator for Open-Drain and Push-Pull Application,SMD,VSSOP8,Runic; Manufacturer: Runic; Myir P/N: 20105.00030; Part Type: Logic; Datasheet: RS0102.pdf
Y3 = Crystal_4P: Crystal,25MHz,+/-10ppm,18pF,4Pin,3225,-40℃to+85℃,SMD,SJK; Manufacturer: SJK; Manufacturer P/N: SJK-7U25000MAH1430B8; Myir P/N: 20901.00029; Part Type: Crystal; RP1 Manufacturer P/N: 7V25000025; RP1 Myir P/N: 20901.00005; RP2 Manufacturer P/N: E3FB25E000012E; RP2 Myir P/N: 20901.00020; Datasheet: 7U25000MAH1430B8.pdf
C113 C116 C122 C130 C132 C138 C147 = Ceramic_Capacitor: Ceramic Capacitor,4.7uF,16V, +/-10%,X5R,0603,Samsung; Manufacturer: Samsung; Manufacturer P/N: CL10A475KO8NNNC; Myir P/N: 20401.80066; Part Type: Ceramic Capacitor; Reserve Value: 4.7uF; Datasheet: Samsung.pdf
C121 C128 C137 C146 = Ceramic_Capacitor: Ceramic Capacitor,27pF,50V,+/-5%,C0G,0402,Fenghua; Manufacturer: Fenghua; Manufacturer P/N: 0402CG270J500NT; Myir P/N: 20401.00097; Part Type: Ceramic Capacitor; Reserve Value: 27pF; Datasheet: FENGHUA-Capacitor.pdf
J9 J10 = S11-ZZ-0319: Connector,RJ45 1X1,10/100/1000 Base-T,LED:L-Green; R-Yellow,Gold Flash,-40 °C~+85°C,UDE; Manufacturer: UDE; Myir P/N: 21118.00010; Part Type: ETH Connector; Datasheet: RJ45-UDE_S11-ZZ-0319(20130-00)-A.pdf
L6 L7 = Inductor: Power Inductor,2.2uH 20%,80mOhm 0.85A ,SMD 2.5*2.0*1.0mm,Sunlord; Manufacturer: Sunlord; Manufacturer P/N: MPH252010S2R2MT; Myir P/N: 20501.00042; Part Type: Power Inductor; Reserve Value: 2.2uH; Datasheet: MPH252010S2R2M.pdf
R137 R138 R153 R174 R175 R192 = Resister: Thick Film Resistor,1.5K,+/-5%,1/16W,-55°C ~ 155°C,SMD,0402,Fenghua; Manufacturer: Fenghua; Manufacturer P/N: RC-02W152JT; Myir P/N: 20301.00194; Part Type: Thick Film Resistor; Reserve Value: 1.5K; Datasheet: FH规格书_2018-07-30.pdf
R146-R150 R182-R187 = Resister: Thick Film Resistor,22R,+/-5%,1/16W,-55°C ~ 155°C,SMD,0402,Fenghua; Manufacturer: Fenghua; Manufacturer P/N: RC-02W220JT; Myir P/N: 20301.00187; Part Type: Thick Film Resistor; Reserve Value: 22R; Datasheet: FH规格书_2018-07-30.pdf
R151 R152 R188 R189 = Resister: Thick Film Resistor,1K,+/-5%,1/16W,-55°C ~ 155°C,SMD,0402,Fenghua; Manufacturer: Fenghua; Manufacturer P/N: RC-02W102JT; Myir P/N: 20301.80389; Part Type: Thick Film Resistor; Reserve Value: 1K; Datasheet: FH规格书_2018-07-30.pdf
R157 R194 = Resister: Thick Film Resistor,1K,+/-5%,1/16W,-55℃~155℃,SMD,0402,Fenghua; Manufacturer: Fenghua; Manufacturer P/N: RC-02W102JT; Myir P/N: 20301.80389; Part Type: Thick Film Resistor; Reserve Value: 1K; Datasheet: FHsheet_2018-07-30.PDF
R158 R195 = Resister: Thick Film Resistor,2.49K,+/- 1%,1/16W,-55°C ~ 155°C,SMD,0402,Fenghua; Manufacturer: Fenghua; Manufacturer P/N: RC-02W2491FT; Myir P/N: 20301.00249; Part Type: Thick Film Resistor; Reserve Value: 2.49K; Datasheet: FH规格书_2018-07-30.pdf
T14-T18 = TP: DESIG: testing PAD; FAB: NA; REF: NA; VAL: NOT POPULATED
U16 U19 = YT8521SH: IC,Ethernet Physical Layer Transceiver,Consumer,10/100/1000M,0~C~+70~C,Commercial,SMD,QFN48,Motorcomm; Manufacturer: Motorcomm; Myir P/N: 20107.00088; Part Type: Interface; Datasheet: YT8531SH_YT8531SC_Datasheet_draft.pdf
U17 U18 U20 U21 = TPD4E1U06: IC,Quad-Channel,High-Speed ESD Protection Device,SMD,SOT23-6,UN; Manufacturer: UN; Myir P/N: 20114.00013; Part Type: Protection; RP1 Manufacturer P/N: TPD4E1U06DBVR; RP1 Myir P/N: 20114.00004; Datasheet: SR05-04A.pdf
Y7 Y8 = Crystal_0: Crystal,25MHz,+/-10ppm,18pF,4Pin,3225,-40℃to+85℃,SMD,SJK; Manufacturer: SJK; Manufacturer P/N: SJK-7U25000MAH1430B8; Myir P/N: 20901.00029; Part Type: Crystal; RP1 Manufacturer P/N: 7V25000025; RP1 Myir P/N: 20901.00005; RP2 Manufacturer P/N: E3FB25E000012E; RP2 Myir P/N: 20901.00020; Datasheet: 7U25000MAH1430B8.pdf
C149 C152 = Ceramic_Capacitor: Ceramic Capacitor,10nF,50V,+/-10%,X7R,0402,Fenghua; Manufacturer: Fenghua; Manufacturer P/N: 0402B103K500NT; Myir P/N: 20401.80103; Part Type: Ceramic Capacitor; Reserve Value: 10nF; Datasheet: FENGHUA-Capacitor.pdf
J17 J18 = U_1.FL-LP-040: RF Connector,1 Contact(s),Male, Board Mount,Surface Mount Terminal,UMCC RCP 0Hz to 6GHz 50Ohm Solder ST SMD Gold Over Nickel,HRS; Manufacturer: HRS; Myir P/N: 21114.80006; Part Type: Antenna Connector; Datasheet: UFL Series.pdf
R211-R215 R236-R240 = RESISTER: Thick Film Resistor,10K,+/-5%,1/16W,-55℃~155℃,SMD,0402,Fenghua; Manufacturer: Fenghua; Manufacturer P/N: RC-02K103JT; Myir P/N: 20301.00199; Part Type: Thick Film Resistor; Reserve Value: 10K; Datasheet: FHsheet-20230524.pdf
R220 = Resister: Thick Film Resistor,100R,+/-5%,1/16W,-55℃~155℃,SMD,0402,Fenghua; Manufacturer: Fenghua; Manufacturer P/N: RC-02K101JT; Myir P/N: 20301.00191; Part Type: Thick Film Resistor; Reserve Value: 100R; Datasheet: FHsheet-20230524.pdf
R222 R234 = RESISTER: Thick Film Resistor,0R,+/-5%,1/16W,-55℃~155℃,SMD,0402,Fenghua; Manufacturer: Fenghua; Manufacturer P/N: RC-02000JT; Myir P/N: 20301.00186; Part Type: Thick Film Resistor; Reserve Value: 0R; Datasheet: FHsheet-20230524.pdf
R229-R231 = Resister: Thick Film Resistor,4.7K,+/-5%,1/16W,-55°C ~ 155°C,SMD,0402,Fenghua; Manufacturer: Fenghua; Manufacturer P/N: RC-02W472JT; Myir P/N: 20301.80393; Part Type: Thick Film Resistor; Reserve Value: 4.7K; Datasheet: FHsheet_2018-07-30.PDF
R232 = Resister: Thick Film Resistor,0R,+/-5%,1/16W,-55°C ~ 155°C,SMD,0402,Fenghua; Manufacturer: Fenghua; Manufacturer P/N: RC-02000JT; Myir P/N: 20301.00186; Part Type: Thick Film Resistor; Reserve Value: 0R; Datasheet: FHsheet_2018-07-30.PDF
R235 = RESISTER: Thick Film Resistor,10K,+/-5%,1/16W,-55°C ~ 155°C,SMD,0402,Fenghua; Manufacturer: Fenghua; Manufacturer P/N: RC-02W103JT; Myir P/N: 20301.00199; Part Type: Thick Film Resistor; Reserve Value: 10K; Datasheet: FHsheet_2018-07-30.PDF
U22 = FG6222BSRC-E0: WIFI/Bluetooth Module,802.11a/b/g/n/ac 2T2R WiFi + Bluetooth 4.2 SDIO Module,-10~70℃,Size 15.1*13.1*2.4mm,SMD,REEL,LB-LINK; Manufacturer: LB-LINK; Myir P/N: 20201.00012; Part Type: WIFI Module; Datasheet: BL-M8822CS1-2.pdf
U23 U24 = SN74CBTLV3257: IC,Low-Voltage 4-Bit 1-of-2 FET Multiplexer,SMD,TSSOP16,CL257,TI; Manufacturer: TI; Myir P/N: 20105.00006; Part Type: Logic; Datasheet: sn74cbtlv3257.pdf
Y9 = Oscillator_4P: Oscillator,32.768KHz,+/-30ppm,15pF,3.3V,4Pin,3225,-40℃to+85℃,SMD,SJK; Manufacturer: SJK; Manufacturer P/N: SJK-3N32768K3C0430B8; Myir P/N: 20902.00010; Part Type: Oscillator; RP1 Manufacturer P/N: HSO321S-32.768KHz; RP1 Myir P/N: 20902.00002; Reserve Value: 32.768kHZ; Datasheet: 3N32768K3C0430B8.pdf

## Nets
GND: C68.2 C69.2 C70.2 C71.2 C73.2 C74.2 C75.2 C76.2 C77.2 C78.2 C79.2 C80.2 C81.2 C82.2 C83.2 C84.2 C85.2 C86.2 C87.2 C88.2 C89.2 C90.2 C91.2 C92.2 C93.2 C94.2 C95.2 C96.2 C103.2 C104.2 C109.2 C110.2 C111.2 C112.2 C113.2 C114.2 C115.2 C116.2 C117.2 C118.2 C119.2 C120.2 C121.1 C122.2 C123.2 C124.2 C125.2 C126.2 C127.2 C128.2 C129.2 C130.2 C131.2 C132.2 C133.2 C134.2 C135.2 C136.2 C137.1 C138.2 C139.2 C140.2 C141.2 C142.2 C143.2 C144.2 C145.2 C146.1 C147.2 C148.2 C149.2 C152.2 C153.2 C154.2 C155.2 C156.2 C157.2 C158.2 D30.1 D31.1 D32.1 D33.1 D34.1 D35.1 J6.7(GND2) J6.10(GND3) J6.13(GND4) J6.16(GND5) J6.19(GND6) J6.22(GND7) J6.25(GND8) J6.30(GND9) J6.41(AGND) J6.42(GND1) J7.2(SHIELD0) J7.5(SHIELD1) J7.8(SHIELD2) J7.11(SHIELD3) J7.17(GND) J9.12(YELLOW-) J9.14(GREEN-) J10.12(YELLOW-) J10.14(GREEN-) J17.2(GND1) J17.3(GND) J18.2(GND1) J18.3(GND) R100.1 R104.1 R105.2 R106.2 R120.1 R132.2 R157.2 R158.1 R165.2 R166.2 R167.2 R168.2 R169.2 R170.2 R171.2 R172.2 R173.2 R194.2 R195.1 R202.2 R203.2 R204.2 R205.2 R206.2 R207.2 R208.2 R209.2 R210.2 R222.1 R233.2 R234.2 R243.1 R244.1 R245.1 R246.1 U11.6(VSSA_MIPIRX) U11.17(VSS) U11.23(VSSA_HDMITX) U11.29(VSSA_HDMITX) U11.32(VSS) U11.36(VSSA_HDMIPLL) U11.42(VSSA_LVDSTX) U11.49(VSSA_SYSCLK) U11.51(VSSA_LVDSPLL) U11.56(VSS) U11.65(GND_EP) U12.B1(GND_CH1) U12.B2(GND_CH2) U13.B1(GND_CH1) U13.B2(GND_CH2) U14.2(GND) U15.4(DGND) U15.29(EPGND) U16.49(GND) U17.2(GND) U18.2(GND) U19.49(GND) U20.2(GND) U21.2(GND) U22.1(GND) U22.3(GND) U22.4(GND) U22.5(GND) U22.6(GND) U22.7(GND) U22.8(GND) U22.10(GND) U22.11(GND) U22.23(GND) U22.32(GND) U22.39(GND) U23.8(GND) U24.8(GND) Y3.2 Y3.4 Y4.2(GND) Y5.2(GND) Y6.2(GND) Y7.2(GND/NC) Y7.4(GND) Y8.2(GND/NC) Y8.4(GND) Y9.2(GND) ; also on sheet 4 5 6 7 12 13 14 15
GND_EARTH: C81.1 J7.20(GND0) J7.21(GND3) J7.22(GND1) J7.23(GND2) J9.15(GND1) J9.16(GND2) J10.15(GND1) J10.16(GND2) R104.2 ; also on sheet 4 6 15
VDD_1V8: FB3.2 FB4.2 Q5.3(C) R76.1 R230.1 ; also on sheet 4 5
VDD_3V3: C90.1 C103.1 C104.1 C113.1 C114.1 C115.1 FB5.1 FB6.1 FB7.1 FB8.1 FB9.2 FB10.1 FB12.2 FB13.1 FB15.1 R83.1 R84.1 R85.1 R107.1 R108.1 R115.1 R137.2 R138.2 R156.2 R162.1 R163.1 R164.1 R174.2 R175.2 R193.2 R199.1 R200.1 R201.1 R241.2 R242.2 U14.3(VCCA) U14.6(OE) U15.2(DVDD) U15.3(PVDD) U23.16(VCC) U24.16(VCC) ; also on sheet 4 5 6 7 12 13
VDD_5V: C68.1 C69.1 C91.1 D25.1 D26.1 J6.2(VCC5V) J6.3(VCC5V) R109.1 R110.1 U14.7(VCCB) ; also on sheet 4 5 6 12 14
VDD_ADC_VREF: C107.1 R130.2 U15.19(ADCVREF)
VDD_BL_3V3: C153.1 C154.1 C155.1 C156.1 FB15.2 R211.2 R212.2 R213.2 R214.2 R215.2 R229.1 R235.2 R236.2 R237.2 R238.2 R239.2 R240.2 U22.34(VDDIO) U22.36(VCC33)
VDD_PHY0_3V3: C116.1 C117.1 C118.1 FB9.1 R154.1 R155.1 U16.30(DVDD33) U16.31(VDD33_LX)
VDD_PHY1_3V3: C132.1 C133.1 C134.1 FB12.1 R190.1 R191.1 U19.30(DVDD33) U19.31(VDD33_LX)
VDD_RGMII0: C130.1 C131.1 R156.1 R159.1 R160.1 R161.1 U16.29(DVDD_RGMII)
VDD_RGMII1: C147.1 C148.1 R193.1 R196.1 R197.1 R198.1 U19.29(DVDD_RGMII)
VDDA_AUDIO_3V3: C101.1 C102.1 FB6.2 U15.16(HPVDD) U15.17(AVDD)
VDDA_PHY0_1V1: C125.1 C126.1 C127.1 FB11.2 U16.4(AVDDL) U16.9(AVDDL) U16.47(AVDDL)
VDDA_PHY0_3V3: C119.1 C120.1 FB10.2 U16.1(AVDD33) U16.12(AVDD33)
VDDA_PHY1_1V1: C143.1 C144.1 C145.1 FB14.2 U19.4(AVDDL) U19.9(AVDDL) U19.47(AVDDL)
VDDA_PHY1_3V3: C135.1 C136.1 FB13.2 U19.1(AVDD33) U19.12(AVDD33)
VDDL_PHY0_1V1: C122.1 C123.1 C124.1 FB11.1 L6.2 U16.22(DVDDL)
VDDL_PHY1_1V1: C138.1 C139.1 C142.1 FB14.1 L7.2 U19.22(DVDDL)
32.7K_CLK: C158.1 R232.2 R233.1 U22.31(LPO)
AUD_MIC: C105.1 D29.2 J8.5 R129.1 R130.1 R131.1
AUDIO1_LOUT_L: C97.1 D27.2 J8.3 R116.2 R124.1
AUDIO1_LOUT_R: C98.1 D28.2 J8.6 R123.2
AUDIO_AGND: C97.2 C98.2 C101.2 C102.2 C105.2 C106.2 C107.2 C108.2 D27.1 D28.1 D29.1 J8.2 R124.2 R127.2 R128.1 R131.2 R132.1 U15.18(AGND)
AUDIO_MCLK: C94.1 R114.2 U15.1(MCLK)
ET0_LED1: R151.2 R163.2 R165.1 U16.36(LED1/CFG_LDO0)
ET0_LED2: R152.2 R164.2 R166.1 U16.37(LED2/CFG_LDO1)
ET0_LINKSTA: R117.1 ; also on sheet 14
ET0_MDC: R137.1 T14.1(TP) U16.14(MDC) ; also on sheet 14
ET0_MDIO: R138.1 U16.15(MDIO) ; also on sheet 14
ET0_PHYAD0: R162.2 R173.1 U16.35(LED0/PHYAD0)
ET0_RX_CTL: R146.2 R160.2 R171.1 ; also on sheet 14
ET0_RXC: R145.2 R161.2 R172.1 ; also on sheet 14
ET0_RXD0: R147.2 R159.2 R170.1 ; also on sheet 14
ET0_RXD1: R148.2 R169.1 ; also on sheet 14
ET0_RXD2: R149.2 R168.1 ; also on sheet 14
ET0_RXD3: R150.2 R167.1 ; also on sheet 14
ET0_TRN0: J9.2(TD1-) U16.3(TRXN0) U17.6(D1-)
ET0_TRN1: J9.4(TD2-) U16.6(TRXN1) U17.4(D2-)
ET0_TRN2: J9.8(TD3-) U16.8(TRXN2) U18.6(D1-)
ET0_TRN3: J9.10(TD4-) U16.11(TRXN3) U18.4(D2-)
ET0_TRP0: J9.1(TD1+) U16.2(TPXP0) U17.1(D1+)
ET0_TRP1: J9.3(TD2+) U16.5(TRXP1) U17.3(D2+)
ET0_TRP2: J9.7(TD3+) U16.7(TRXP2) U18.1(D1+)
ET0_TRP3: J9.9(TD4+) U16.10(TRXP3) U18.3(D2+)
ET0_TX_CTL: R141.2 ; also on sheet 14
ET0_TXC: R140.2 ; also on sheet 14
ET0_TXD0: R142.2 ; also on sheet 14
ET0_TXD1: R143.2 ; also on sheet 14
ET0_TXD2: R144.2 ; also on sheet 14
ET0_TXD3: R139.2 ; also on sheet 14
ET1_LED1: R188.2 R200.2 R202.1 U19.36(LED1/CFG_LDO0)
ET1_LED2: R189.2 R201.2 R203.1 U19.37(LED2/CFG_LDO1)
ET1_MDC: R174.1 T16.1(TP) U19.14(MDC) ; also on sheet 14
ET1_MDIO: R175.1 U19.15(MDIO) ; also on sheet 14
ET1_PHYAD0: R199.2 R210.1 U19.35(LED0/PHYAD0)
ET1_RX_CTL: R183.2 R197.2 R208.1 ; also on sheet 14
ET1_RXC: R182.2 R198.2 R209.1 ; also on sheet 14
ET1_RXD0: R184.2 R196.2 R207.1 ; also on sheet 14
ET1_RXD1: R185.2 R206.1 ; also on sheet 14
ET1_RXD2: R186.2 R205.1 ; also on sheet 14
ET1_RXD3: R187.2 R204.1 ; also on sheet 14
ET1_TRN0: J10.2(TD1-) U19.3(TRXN0) U20.6(D1-)
ET1_TRN1: J10.4(TD2-) U19.6(TRXN1) U20.4(D2-)
ET1_TRN2: J10.8(TD3-) U19.8(TRXN2) U21.6(D1-)
ET1_TRN3: J10.10(TD4-) U19.11(TRXN3) U21.4(D2-)
ET1_TRP0: J10.1(TD1+) U19.2(TPXP0) U20.1(D1+)
ET1_TRP1: J10.3(TD2+) U19.5(TRXP1) U20.3(D2+)
ET1_TRP2: J10.7(TD3+) U19.7(TRXP2) U21.1(D1+)
ET1_TRP3: J10.9(TD4+) U19.10(TRXP3) U21.3(D2+)
ET1_TX_CTL: R180.2 ; also on sheet 14
ET1_TXC: R176.2 ; also on sheet 14
ET1_TXD0: R177.2 ; also on sheet 14
ET1_TXD1: R181.2 ; also on sheet 14
ET1_TXD2: R178.2 ; also on sheet 14
ET1_TXD3: R179.2 ; also on sheet 14
HPD_DET: J7.19(HOTPLUG) R103.1 R106.1
HPGND: R127.1 U15.13(HPGND)
INT: R80.2 U11.63(INT)
LT8912_VCCA_HDMIPLL: C72.2 C82.1 C83.1 C84.1 C85.1 C88.1 C89.1 FB4.1 U11.34(VCCA_HDMIPLL) U11.50(VCCA_SYSCLK) U11.52(VCCA_LVDSPLL)
LT8912_VCCA_HDMITX: C73.1 C74.1 C75.1 C76.1 C77.1 C78.1 C79.1 C80.1 C86.1 C87.1 FB3.1 U11.5(VCCA_MIPIRX) U11.18(VDD) U11.26(VCCA_HDMITX) U11.33(VDD) U11.41(VCCA_LVDSTX) U11.57(VDD)
LVDS_CLK+: J6.18(RXCLK+) U11.39(LVDSTX_CKP)
LVDS_CLK-: J6.17(RXXLK-) U11.40(LVDSTX_CKN)
LVDS_D0+: J6.9(RXIN0+) U11.47(LVDSTX0_DP)
LVDS_D0-: J6.8(RXIN0-) U11.48(LVDSTX0_DN)
LVDS_D1+: J6.12(RXIN1+) U11.45(LVDSTX1_DP)
LVDS_D1-: J6.11(RXIN1-) U11.46(LVDSTX1_DN)
LVDS_D2+: J6.15(RXIN2+) U11.43(LVDSTX2_DP)
LVDS_D2-: J6.14(RXIN2-) U11.44(LVDSTX2_DN)
LVDS_D3+: J6.21(RXIN3+) U11.37(LVDSTX3_DP)
LVDS_D3-: J6.20(RXIN3-) U11.38(LVDSTX3_DN)
Reserved0: U16.43(RESERVED1)
Reserved1: U19.43(RESERVED1)
RIIC0_SCL_1V8: R79.1 ; also on sheet 5
RIIC0_SDA_1V8: R78.1 ; also on sheet 5
RIIC1_SCL_5V: J7.15(SCL) R102.2 R109.2 U14.8(B1)
RIIC1_SDA_5V: J7.16(SDA) R101.2 R110.2 U14.1(B2)
RZ_AUDIO_CLK_11_2896M: R134.2 ; also on sheet 14
RZ_AUDIO_CLK_12_2880M: R136.2 ; also on sheet 14
RZ_DISP_DATA0: R212.1 U22.44(SD_RESET) ; also on sheet 14
RZ_DISP_DATA1: R213.1 U22.38(BT_REG_ON) ; also on sheet 14
RZ_DISP_DATA3: R216.2 ; also on sheet 14
RZ_DISP_DATA4: R217.2 ; also on sheet 14
RZ_DISP_DATA6: R242.1 R246.2 U23.1(S) ; also on sheet 14
RZ_DISP_DATA7: R245.2 U23.15(nOE) ; also on sheet 14
RZ_DISP_DATA8: R241.1 R244.2 U24.1(S) ; also on sheet 14
RZ_DISP_DATA9: R243.2 U24.15(nOE) ; also on sheet 14
RZ_DISP_DATA22: R215.1 U22.16(WL_WAKE_HOST) ; also on sheet 14
RZ_DISP_DATA23: R214.1 U22.50(BT_WAKE_HOST) ; also on sheet 14
RZ_DSI_CLK_N: R95.2 ; also on sheet 14
RZ_DSI_CLK_P: R93.2 ; also on sheet 14
RZ_DSI_DATA0_N: R82.2 ; also on sheet 14
RZ_DSI_DATA0_P: R88.2 ; also on sheet 14
RZ_DSI_DATA1_N: R90.2 ; also on sheet 14
RZ_DSI_DATA1_P: R89.2 ; also on sheet 14
RZ_DSI_DATA2_N: R97.2 ; also on sheet 14
RZ_DSI_DATA2_P: R96.2 ; also on sheet 14
RZ_DSI_DATA3_N: R99.2 ; also on sheet 14
RZ_DSI_DATA3_P: R98.2 ; also on sheet 14
RZ_P16_1_1V8: R76.2 R80.1 ; also on sheet 5
RZ_P42_2_1V8: R81.1 ; also on sheet 5
RZ_P42_3: R84.2 R87.1 ; also on sheet 14
RZ_P43_0: R83.2 R86.1 ; also on sheet 14
RZ_P43_2: R190.2 U19.34(INT_N/PME_N) ; also on sheet 14
RZ_P43_3: R191.2 R194.1 U19.13(RESET_N) ; also on sheet 14
RZ_P44_2: R154.2 U16.34(INT_N/PME_N) ; also on sheet 14
RZ_P44_3: R155.2 R157.1 U16.13(RESET_N) ; also on sheet 14
RZ_P48_2: R85.2 R94.1 ; also on sheet 14
RZ_RIIC0_SCL: R92.1 ; also on sheet 5 6 14
RZ_RIIC0_SDA: R91.1 ; also on sheet 5 6 14
RZ_RIIC1_SCL: R108.2 R111.1 R118.1 ; also on sheet 12 14
RZ_RIIC1_SDA: R107.2 R112.1 R119.1 ; also on sheet 12 14
RZ_SCIF1_CTS: R220.2 ; also on sheet 14
RZ_SCIF1_RTS: R221.2 ; also on sheet 14
RZ_SCIF1_RXD: R218.2 ; also on sheet 14
RZ_SCIF1_TXD: R219.2 ; also on sheet 14
RZ_SD1_CLK: U24.7(2A) ; also on sheet 14
RZ_SD1_CMD: U24.4(1A) ; also on sheet 14
RZ_SD1_D0: U23.4(1A) ; also on sheet 14
RZ_SD1_D1: U23.7(2A) ; also on sheet 14
RZ_SD1_D2: U23.9(3A) ; also on sheet 14
RZ_SD1_D3: U23.12(4A) ; also on sheet 14
RZ_SSI0_BCK: R121.1 ; also on sheet 14
RZ_SSI0_RCK: R122.1 ; also on sheet 14
RZ_SSI0_RXD: R126.1 ; also on sheet 14
RZ_SSI0_TXD: R125.1 ; also on sheet 14
RZ_SSI1_BCK_1V8: U11.60(SCLK_I) ; also on sheet 5
RZ_SSI1_RCK_1V8: U11.59(WS_I/SPDIF_IN) ; also on sheet 5
RZ_SSI1_TXD_1V8: U11.58(SD0_CEC) ; also on sheet 5
SD1_CLK: U24.5(2B1) ; also on sheet 7
SD1_CMD: U24.2(1B1) ; also on sheet 7
SD1_D0: U23.2(1B1) ; also on sheet 7
SD1_D1: U23.5(2B1) ; also on sheet 7
SD1_D2: U23.11(3B1) ; also on sheet 7
SD1_D3: U23.14(4B1) ; also on sheet 7
SDIO_CLK: R223.1 R235.1 U22.18(SDIO_CLK)
SDIO_CMD: R224.1 R236.1 U22.17(SDIO_CMD)
SDIO_DATA0: R225.1 R237.1 U22.21(SDIO_CDATA_0)
SDIO_DATA1: R226.1 R238.1 U22.22(SDIO_CDATA_1)
SDIO_DATA2: R227.1 R239.1 U22.20(SDIO_CDATA_2)
SDIO_DATA3: R228.1 R240.1 U22.19(SDIO_CDATA_3)
TX0_DN: U11.24(HDMITX0_DN) U13.C2(CH1_OUT-)
TX0_DN_OUT: J7.9(D0-) U13.A2(CH1_IN-)
TX0_DP: U11.25(HDMITX0_DP) U13.C1(CH1_OUT+)
TX0_DP_OUT: J7.7(D0+) U13.A1(CH1_IN+)
TX1_DN: U11.27(HDMITX1_DN) U12.C4(CH2_OUT-)
TX1_DN_OUT: J7.6(D1-) U12.A4(CH2_IN-)
TX1_DP: U11.28(HDMITX1_DP) U12.C3(CH2_OUT+)
TX1_DP_OUT: J7.4(D1+) U12.A3(CH2_IN+)
TX2_DN: U11.30(HDMITX2_DN) U12.C2(CH1_OUT-)
TX2_DN_OUT: J7.3(D2-) U12.A2(CH1_IN-)
TX2_DP: U11.31(HDMITX2_DP) U12.C1(CH1_OUT+)
TX2_DP_OUT: J7.1(D2+) U12.A1(CH1_IN+)
TX_CKN: U11.21(HDMITX_CKN) U13.C4(CH2_OUT-)
TX_CKN_OUT: J7.12(CLK-) U13.A4(CH2_IN-)
TX_CKP: U11.22(HDMITX_CKP) U13.C3(CH2_OUT+)
TX_CKP_OUT: J7.10(CLK+) U13.A3(CH2_IN+)
Tx_HPD: Q5.2(E) R105.1 U11.14(HPD_CBUS)
UART_CTS: R220.1 R222.2 U22.42(UART_RTS_N)
UART_RTS: R221.1 U22.43(UART_CTS_N)
WIFI_SD1_CLK: R223.2 U24.6(2B2)
WIFI_SD1_CMD: R224.2 U24.3(1B2)
WIFI_SD1_D0: R225.2 U23.3(1B2)
WIFI_SD1_D1: R226.2 U23.6(2B2)
WIFI_SD1_D2: R227.2 U23.10(3B2)
WIFI_SD1_D3: R228.2 U23.13(4B2)
N24681904: D26.2 R101.1 R102.1
N24681967: D25.2 J7.18(+5V)
N24681971: Q5.1(B) R103.2
N24683528: R111.2 U14.5(A1)
N24683530: R112.2 U14.4(A2)
N24696102: R147.1 U16.26(RXD0/RXDLY)
N24696119: R150.1 U16.23(RXD3/CFG_MODE2)
N24696121: R149.1 U16.24(RXD2/CFG_MODE1)
N24696123: R148.1 U16.25(RXD1/CFG_MODE0)
N24696137: R145.1 U16.28(RX_CLK/PHYAD1)
N24696177: C121.2 R153.1 U16.45(XTAL_I) Y7.3
N24696297: C128.1 R153.2 U16.46(XTAL_O) Y7.1
N24696307: R158.2 U16.48(RBIAS)
N24696859: R142.1 U16.19(TXD0)
N24696861: R140.1 T15.1(TP) U16.21(TX_CLK)
N24696875: R143.1 U16.18(TXD1)
N24696881: R139.1 U16.16(TXD3)
N24696883: R144.1 U16.17(TXD2)
N24697239: L6.1 U16.32(LX)
N24775120: D30.2 J9.11(YELLOW+) R151.1
N24775122: D31.2 J9.13(GREEN+) R152.1
N24775176: C129.1 J9.5(CT1) J9.6(CT2)
N24790962: R141.1 U16.20(TX_CTL)
N24791040: R146.1 U16.27(RX_CTL/PHYAD2)
N24806528: C137.2 R192.1 U19.45(XTAL_I) Y8.3
N24806541: C146.2 R192.2 U19.46(XTAL_O) Y8.1
N24806543: R195.2 U19.48(RBIAS)
N24806599: L7.1 U19.32(LX)
N24806654: D32.2 J10.11(YELLOW+) R188.1
N24806656: D33.2 J10.13(GREEN+) R189.1
N24806876: C140.1 J10.5(CT1)
N24806931: R180.1 U19.20(TX_CTL)
N24806933: R183.1 U19.27(RX_CTL/PHYAD2)
N24807160: R184.1 U19.26(RXD0/RXDLY)
N24807177: R187.1 U19.23(RXD3/CFG_MODE2)
N24807179: R186.1 U19.24(RXD2/CFG_MODE1)
N24807181: R185.1 U19.25(RXD1/CFG_MODE0)
N24807187: R182.1 T18.1(TP) U19.28(RX_CLK/PHYAD1)
N24807847: R177.1 U19.19(TXD0)
N24807849: R176.1 T17.1(TP) U19.21(TX_CLK)
N24807859: R181.1 U19.18(TXD1)
N24807877: R179.1 U19.16(TXD3)
N24807879: R178.1 U19.17(TXD2)
N25256263: C141.1 J10.6(CT2)
N25318172: C70.1 R77.1 U11.54(XTALO) Y3.3
N25318239: C71.1 R77.2 U11.53(XTALI) Y3.1
N25318297: R78.2 U11.61(S_SDA)
N25318324: R79.2 U11.62(S_SCL)
N25318354: R81.2 U11.64(RESET_N)
N25318494: R88.1 U11.1(MIPIRX0_DP)
N25318514: R82.1 U11.2(MIPIRX0_DN)
N25318534: R89.1 U11.3(MIPIRX1_DP)
N25318541: R90.1 U11.4(MIPIRX1_DN)
N25318586: R93.1 U11.7(MIPIRX_CKP)
N25318611: R95.1 U11.8(MIPIRX_CKN)
N25318630: R96.1 U11.9(MIPIRX2_DP)
N25318650: R97.1 U11.10(MIPIRX2_DN)
N25318670: R98.1 U11.11(MIPIRX3_DP)
N25318677: R99.1 U11.12(MIPIRX3_DN)
N25318682: R100.2 U11.13(R6K)
N25318705: C72.1 U11.35(LPF)
N25530830: C111.1 C112.1 FB8.2 R135.1 Y6.4(VCC)
N25530834: R135.2 Y6.1(EN)
N25530860: R136.1 Y6.3(OUT)
N25531113: C109.1 C110.1 FB7.2 R133.1 Y5.4(VCC)
N25531117: R133.2 Y5.1(EN)
N25531143: R134.1 Y5.3(OUT)
N25931049: J6.27(BL_CTR) R86.2
N25931053: J6.33(TP_MOSI) R91.2
N25931055: J6.34(TP_SCK) R92.2
N25931057: J6.36(TP_PEN) R94.2
N25931062: J6.28(TP_CS) R87.2
N26044739: R234.1 U22.46(NC9) U22.48(NC11)
N26044834: C149.1 C150.2 D34.2 J18.1(SIG)
N26044878: C151.2 C152.1 D35.2 J17.1(SIG)
N26044892: C150.1 U22.9(RF0)
N26044934: R211.1 R217.1 U22.15(WL_REG_ON)
N26045129: R219.1 U22.41(UART_RXD)
N26045131: R218.1 U22.40(UART_TXD)
N26045353: R231.2 Y9.1(EN/Vcont/NC)
N26045371: C157.1 R229.2 R230.2 R231.1 Y9.4(VCC/Vdd)
N26045413: R232.1 Y9.3(OUT/Output)
N26045441: R216.1 U22.49(HOST_WAKE_BT)
N26045646: C151.1 U22.2(RF1)
N26048215: CT2.1 U15.11(ROUT1)
N26048218: CT1.1 U15.12(LOUT1)
N26048225: R121.2 U15.5(SCLK)
N26048227: R122.2 U15.7(LRCK)
N26048236: C96.1 R119.2 U15.27(CDATA)
N26048238: C95.1 R118.2 U15.28(CCLK)
N26048526: R115.2 R117.2 R120.2 U15.26(CE)
N26048542: C108.1 U15.20(VMID)
N26048550: C106.1 U15.10(VREF)
N26048576: C100.1 R129.2
N26048711: R126.2 U15.8(ASDOUT)
N26048728: R125.2 U15.6(DSDIN)
N26048948: C99.2 U15.23(RIN1)
N26048966: C99.1 R128.2
N26049021: C100.2 U15.24(LIN1)
N26049089: CT1.2 R116.1
N26049137: CT2.2 R123.1
N26081452: C92.1 C93.1 FB5.2 R113.1 Y4.4(VCC)
N26081456: R113.2 Y4.1(EN)
N26081482: R114.1 Y4.3(OUT)

Not connected (* = marked no-connect by the designer): J6 1(NC1) 4(NC2) 5(NC3) 6(NC4) 23(NC5) 24(NC6) 26(NC7) 29(NC8) 31(NC9) 32(NC0) 35(NC10) 37(NC11) 38(NC12) 39(NC13) 40(NC14); J7 13(CEC)* 14(NC)*; J8 4 7; U11 15(VBUS)* 16(USB_ID)* 19(USB_DP)* 20(USB_DM)* 55(REFCLK)*; U15 9(NC1) 14(ROUT2) 15(LOUT2) 21(RIN2) 22(LIN2) 25(NC2); U16 33(RESERVED2) 38(HSIP) 39(HSIN) 40(HSOP) 41(HSON) 42(NC) 44(CLKOUT)*; U17 5(NC); U18 5(NC)*; U19 33(RESERVED2) 38(HSIP) 39(HSIN) 40(HSOP) 41(HSON) 42(NC) 44(CLKOUT)*; U20 5(NC); U21 5(NC); U22 12(BL_TRX) 13(NC1) 14(NC2) 24(WL_WAKE_HOST/OOB) 25(NC3) 26(NC4) 27(PCM_SYNC) 28(PCM_IN) 29(PCM_OUT) 30(PCM_CLK) 33(NC5) 35(NC6) 37(NC7) 45(NC8) 47(NC10); U24 9(3A)* 10(3B2)* 11(3B1)* 12(4A)* 13(4B2)* 14(4B1)*

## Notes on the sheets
sheet 8
- MIPI-DSI - HDMI & LVDS
- 7' LVDS  output
- 1.8V
- IRQ4
- 1.8V
- The best choice for R217
  is 6.04K precision resistance.
- because LT8912B no DDC channel,
  so HDMI out no HDCP;
  HDMI DDC should connect to MCU
  or other main chip for read sink EDID.
- HDMI output
- De-couple cap
- 230mA @1.8V， LT8912
- Level-Shifting
sheet 9
- SAI - Audio
- ADDRESS  OX20
  ADDRESS  OX21
- Output 11.2896M clock to the core board
- Output 12.2880M clock to the core board
sheet 10
- RGMII ENET0
- O
- I
- RXC Delay Enable
- RXD[3:1]
  3'b000
  3'b001
  3'b010
  3'b011
  3'b100
  3'b101
  3'b110
  3'b11
- Operation Mode
  UTP <=> RGMII
  FIBER <=> RGMII
  UTP/FIBER <=> RGMII
  UTP <=> SGMII
  SGMII (PHY) <=> RGMII
  SGMII (MAC) <=> RGMII
  UTP <=> FIBER (AUTO)
  UTP <=> FIBER (FORCE)
- PHYAD2
- 1
- 0
- PHYAD1
- 0
- 0
- PHYAD0
- 0
- PHYAD:4
- RGMII ENET1
- O
- I
- RXC Delay Enable
- 0
- 0
- Select external 3.3V
- PHYAD2
- 1
- RXD[3:1]
  3'b000
  3'b001
  3'b010
  3'b011
  3'b100
  3'b101
  3'b110
  3'b11
- PHYAD1
- 1
- Operation Mode
  UTP <=> RGMII
  FIBER <=> RGMII
  UTP/FIBER <=> RGMII
  UTP <=> SGMII
  SGMII (PHY) <=> RGMII
  SGMII (MAC) <=> RGMII
  UTP <=> FIBER (AUTO)
  UTP <=> FIBER (FORCE)
- PHYAD0
- 0
- PHYAD:6
sheet 11
- WIFI  & BL
- WIFI
- IRQ7
- BLE
- IRQ6
- R234 use to BL-M8822CS1S
